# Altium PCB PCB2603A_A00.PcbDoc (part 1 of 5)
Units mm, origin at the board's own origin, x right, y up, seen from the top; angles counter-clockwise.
Board outline 35.56 x 55.88 mm, 8 copper layers (Top Layer, Signal Layer 1, Signal Layer 2, Signal Layer 3, Signal Layer 4, Signal Layer 5, Signal Layer 6, Bottom Layer), stack 1.497 mm thick; 167 components, 113 nets, 4957 pads, 645 vias.
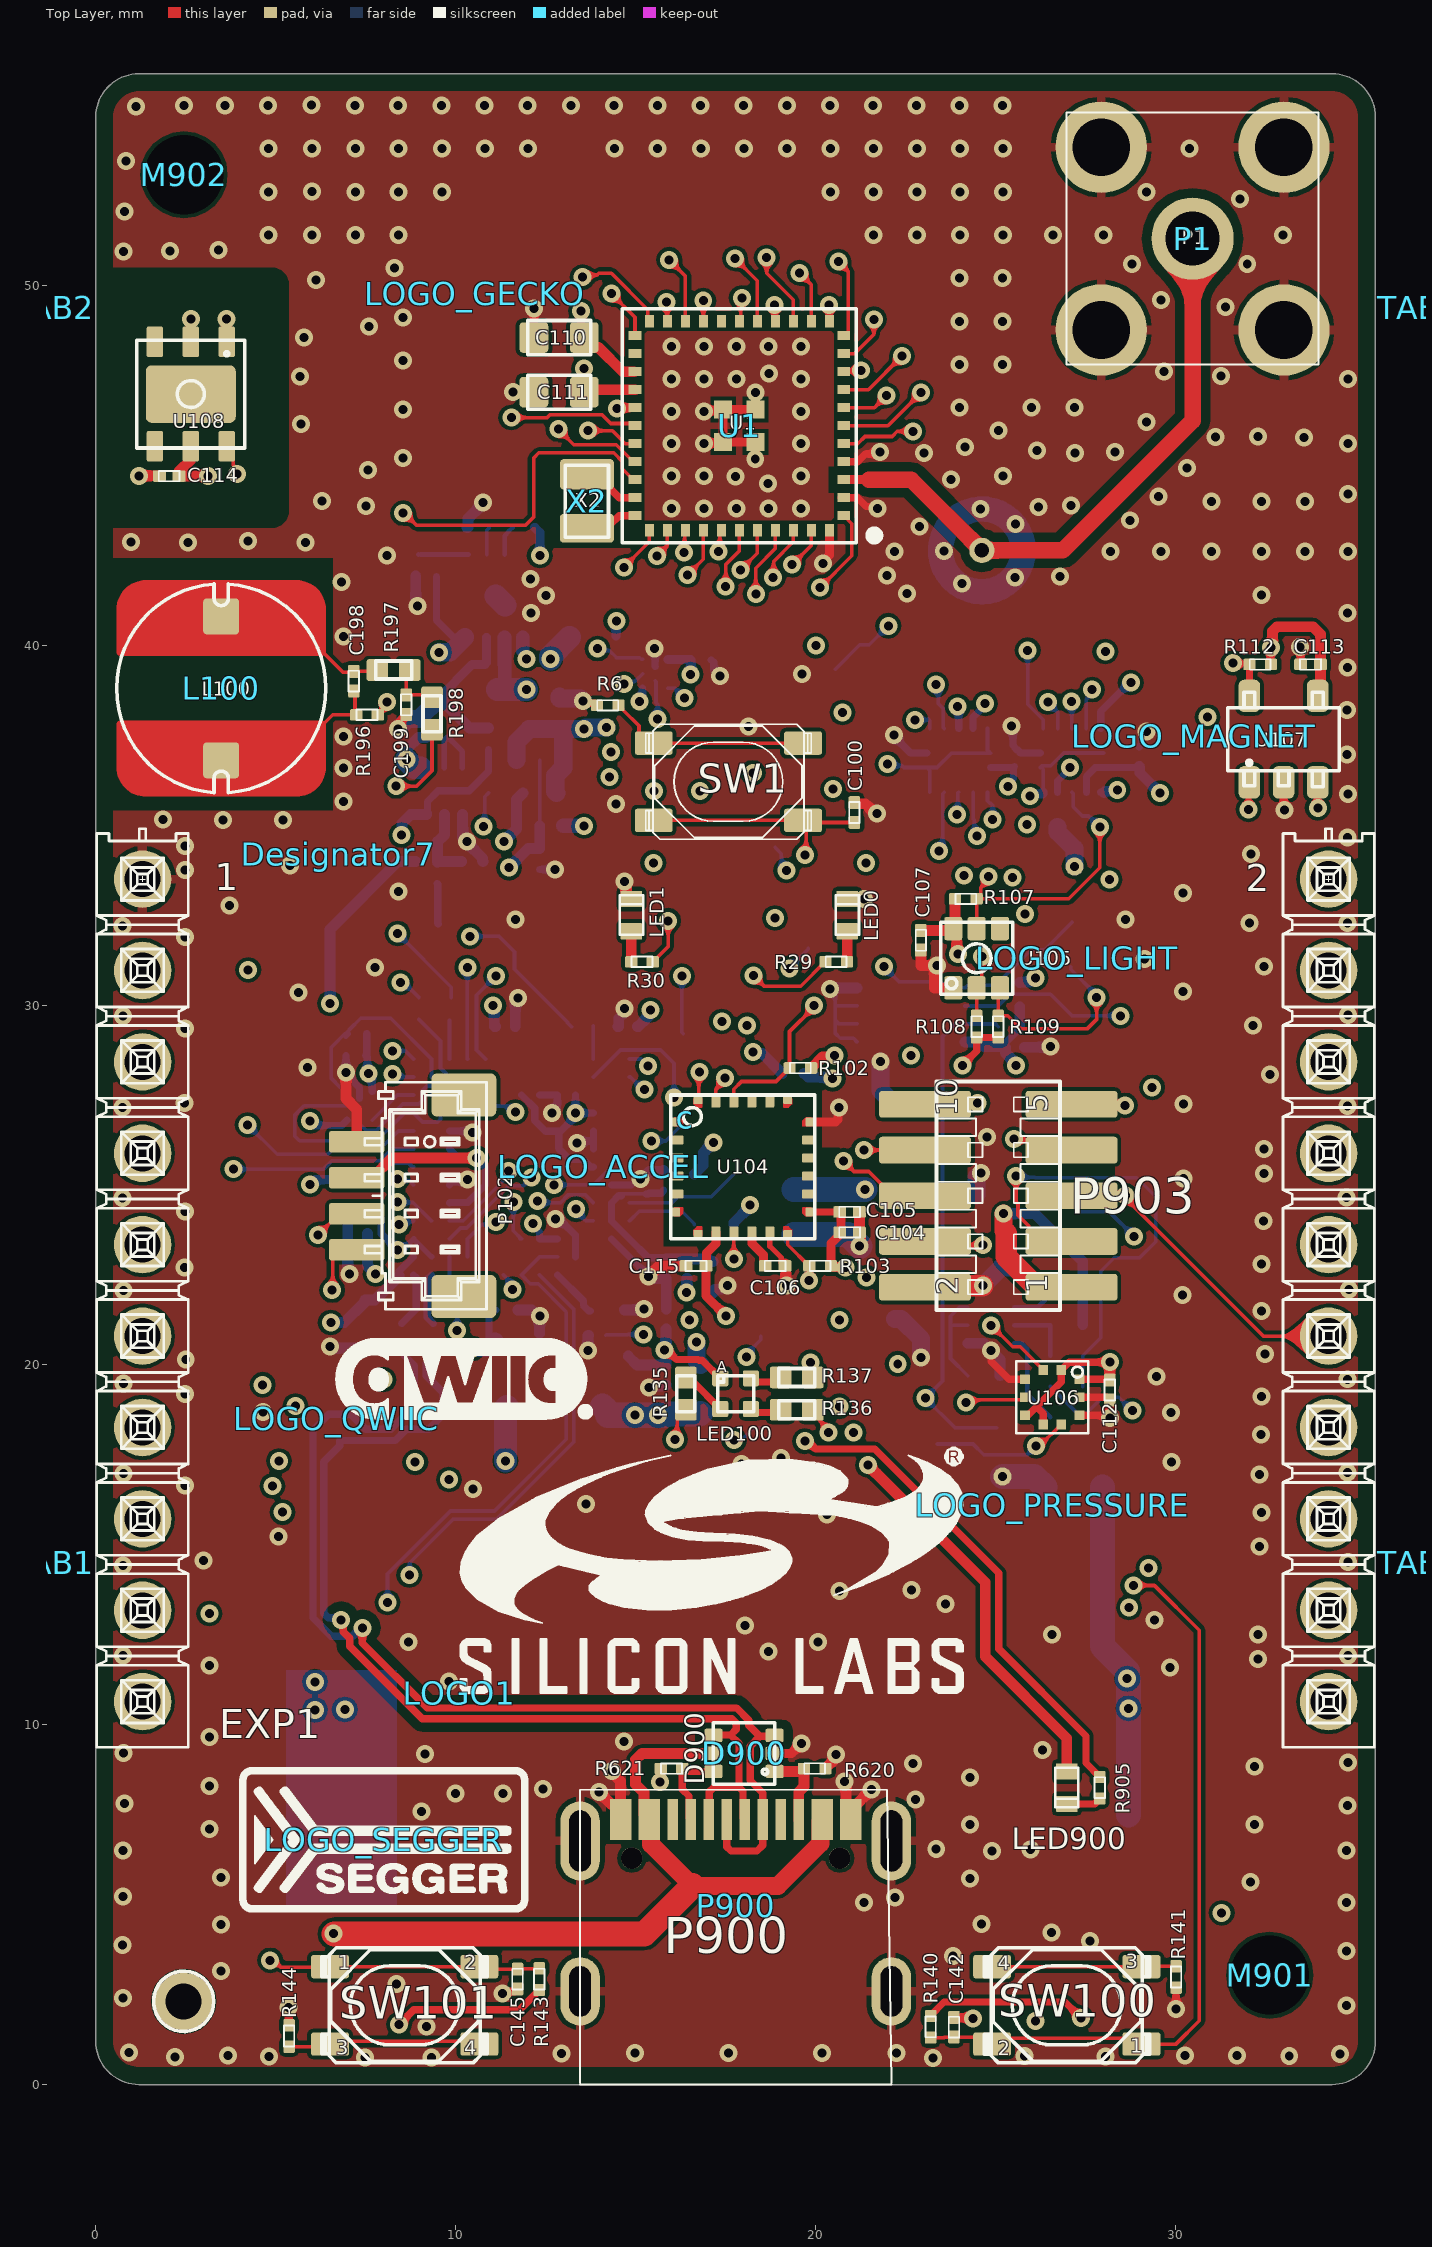
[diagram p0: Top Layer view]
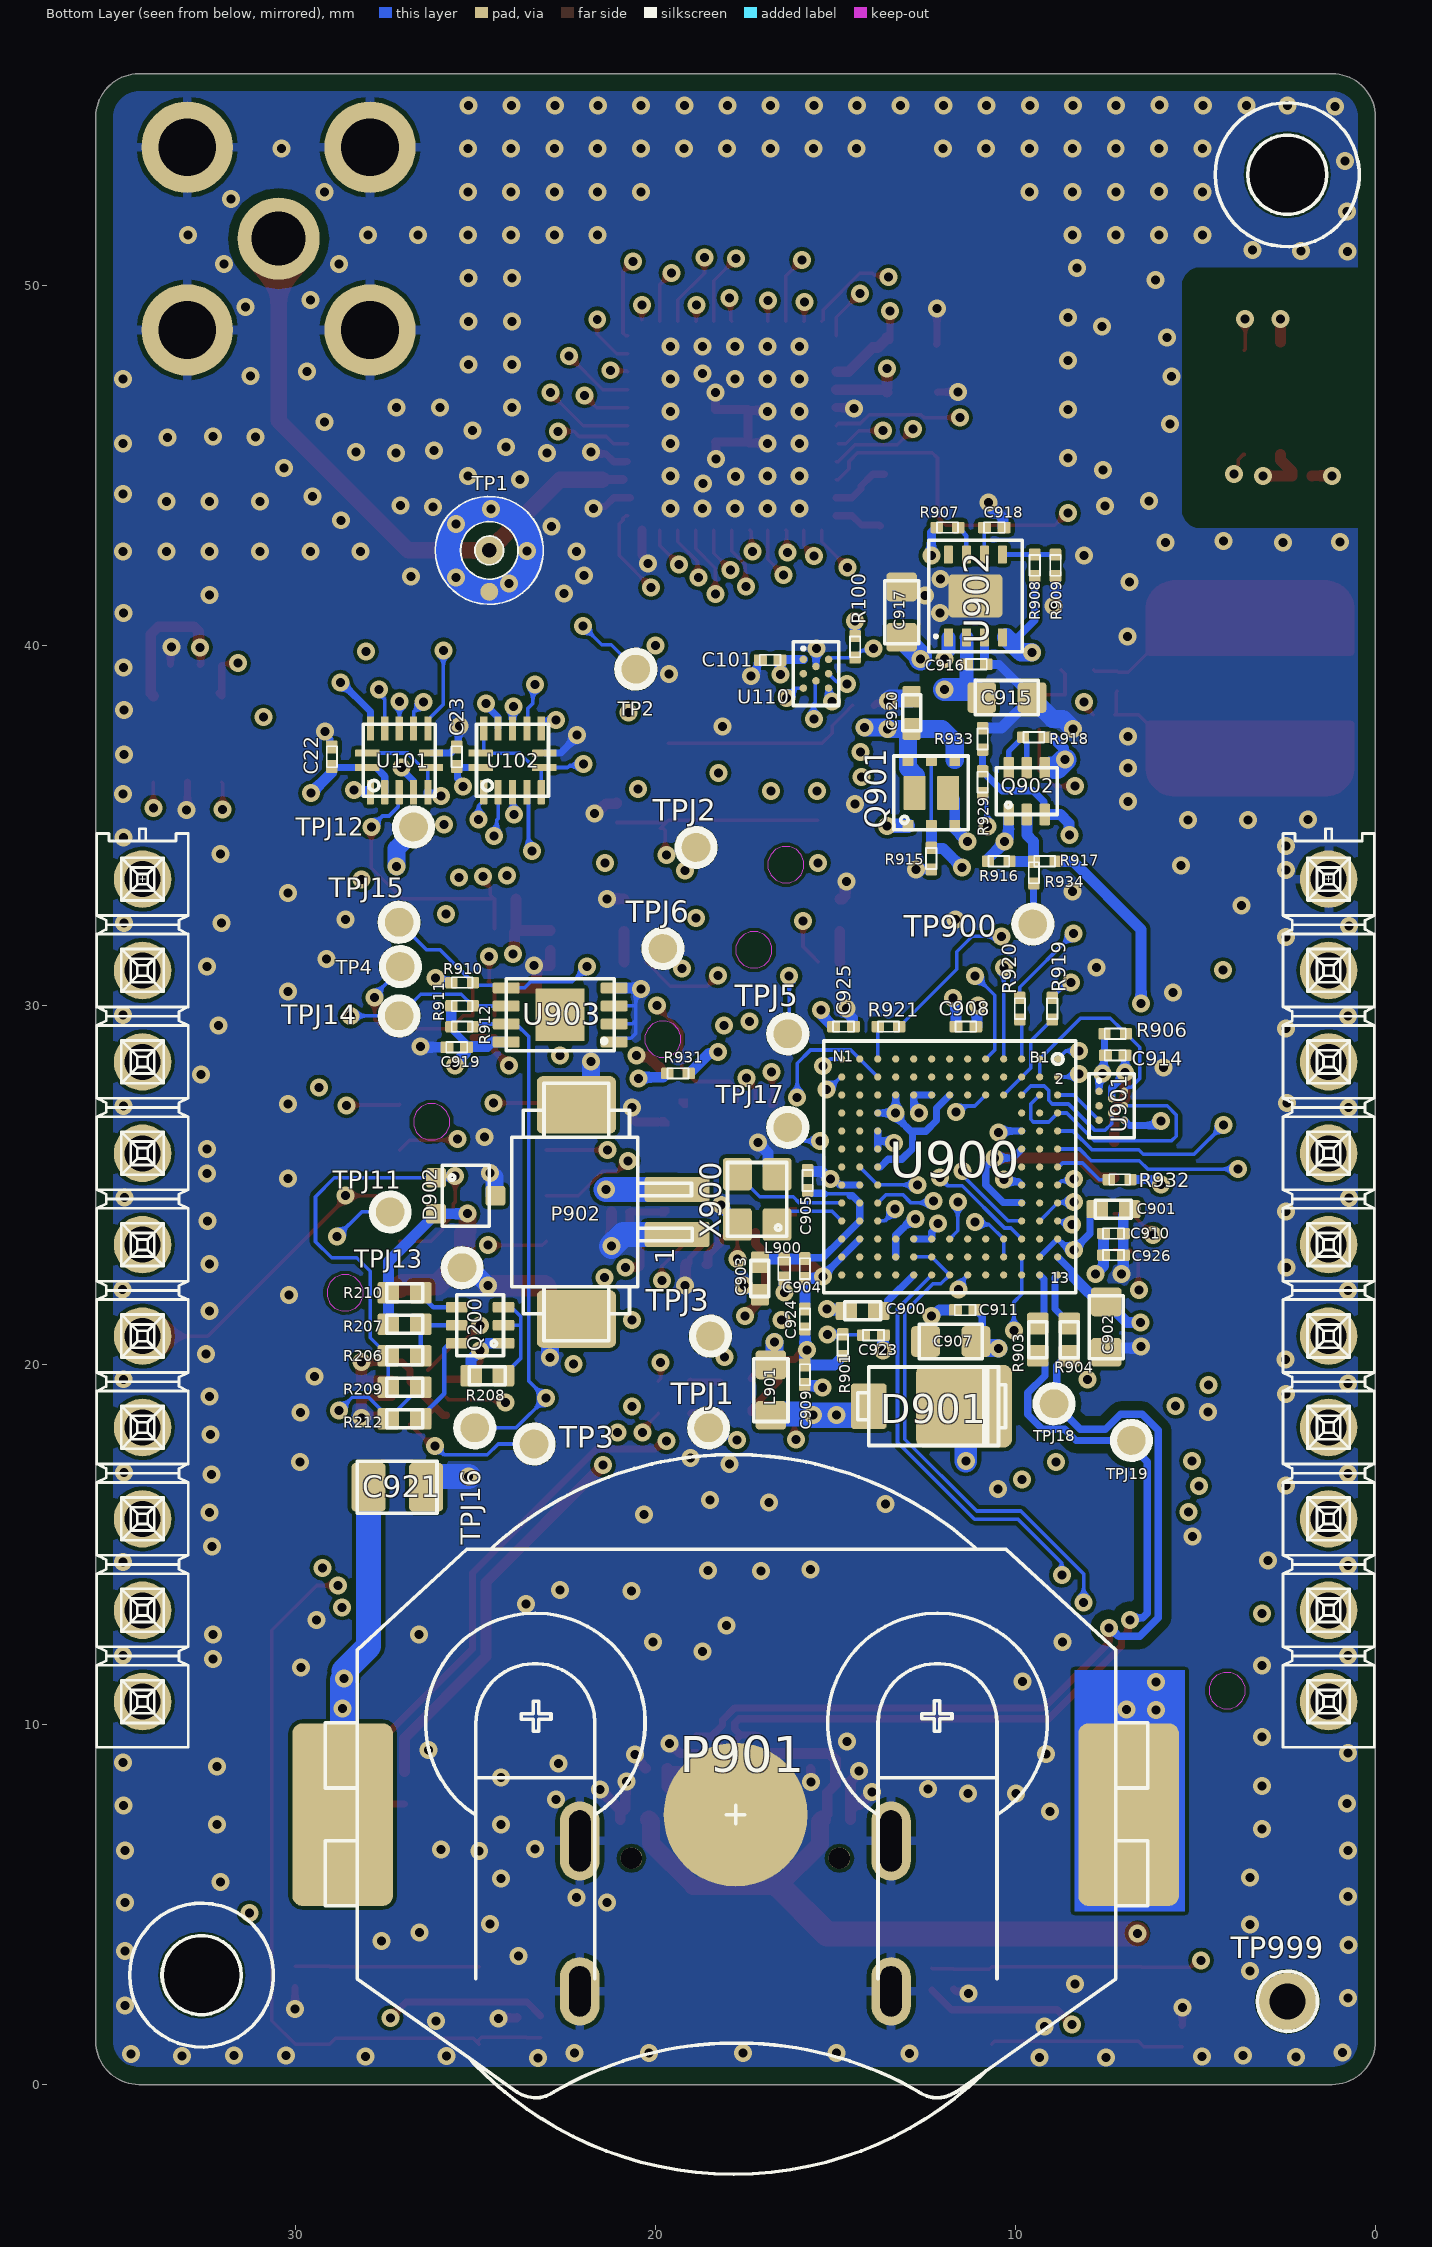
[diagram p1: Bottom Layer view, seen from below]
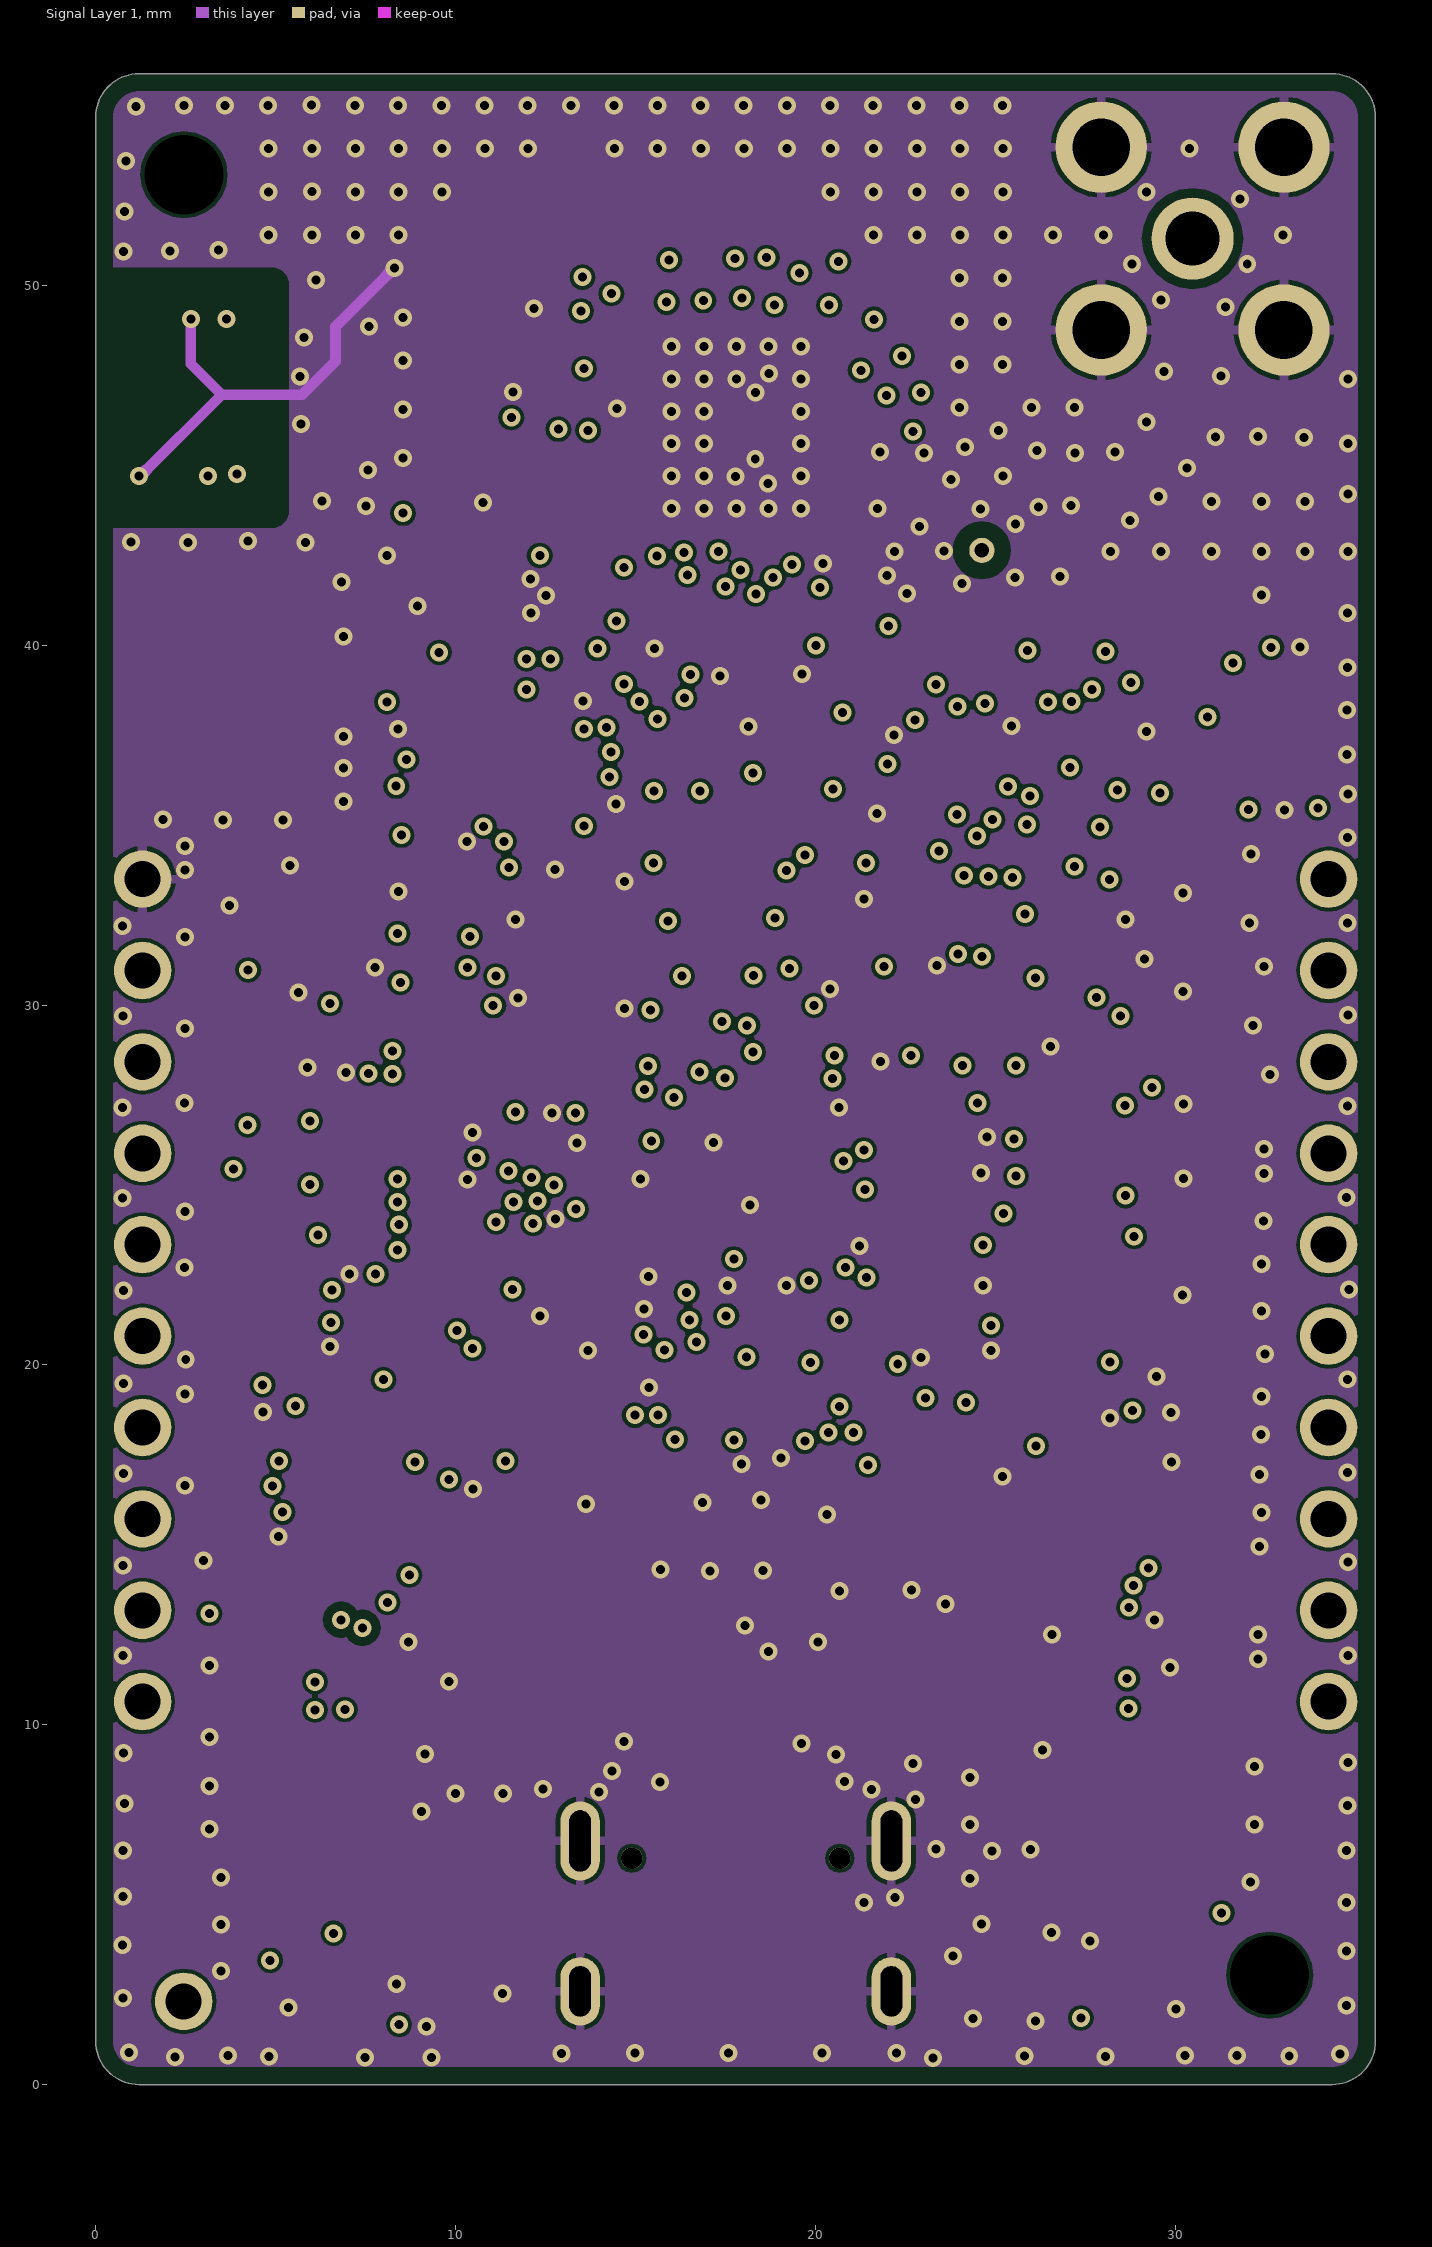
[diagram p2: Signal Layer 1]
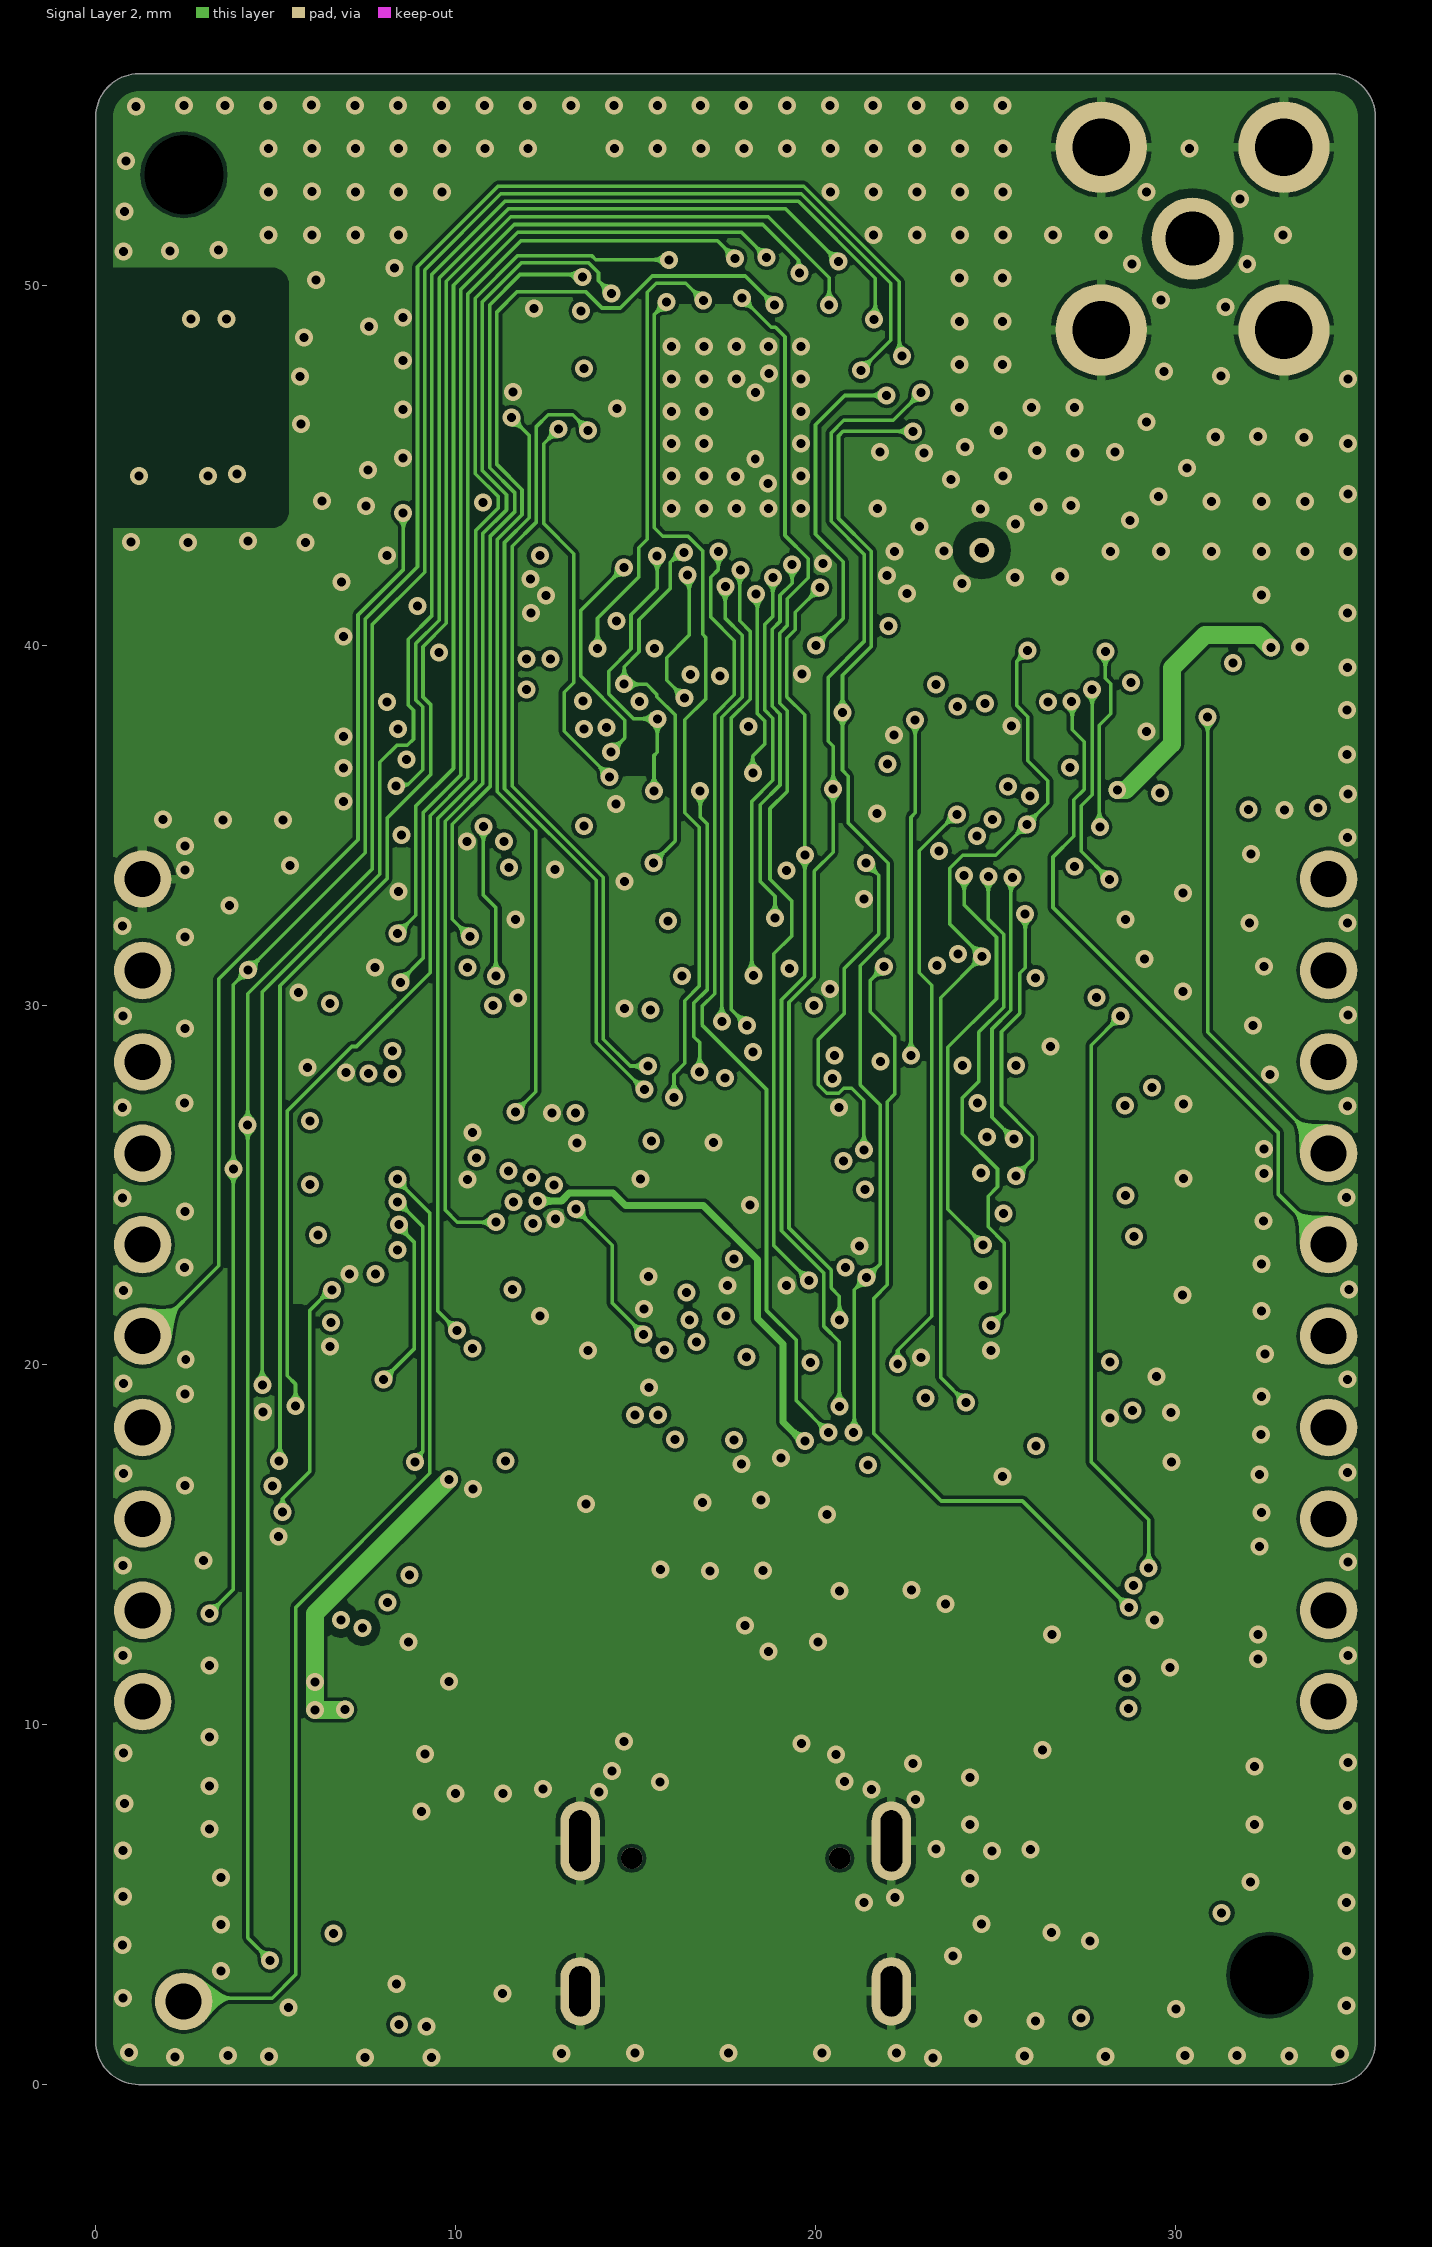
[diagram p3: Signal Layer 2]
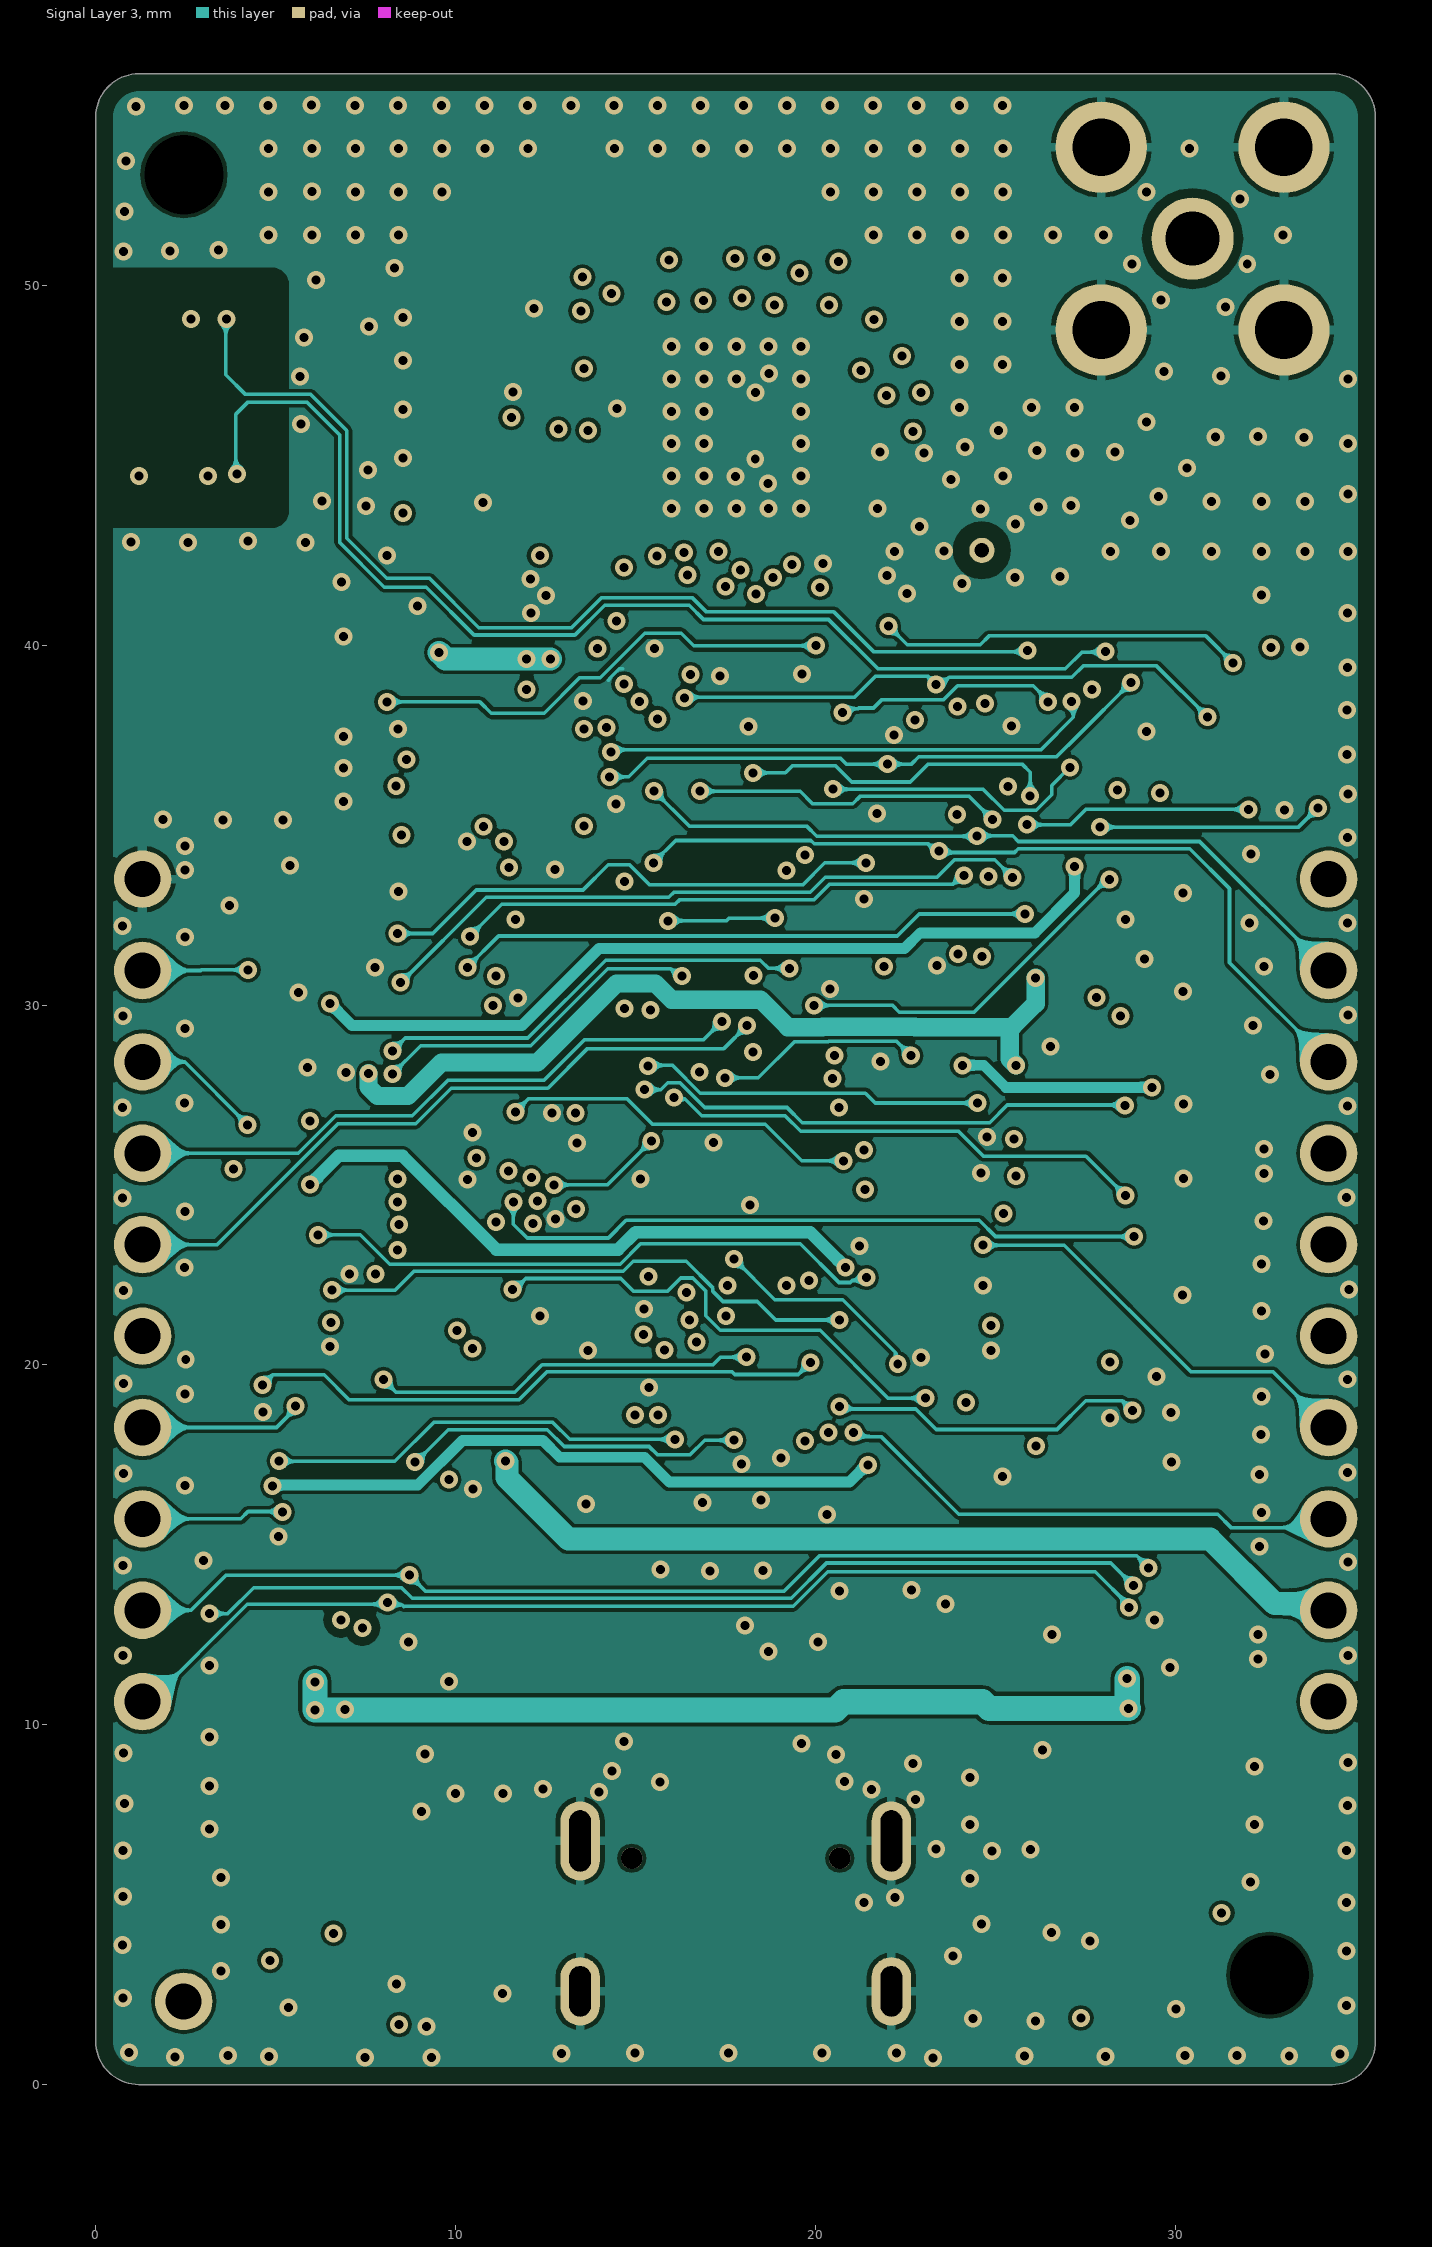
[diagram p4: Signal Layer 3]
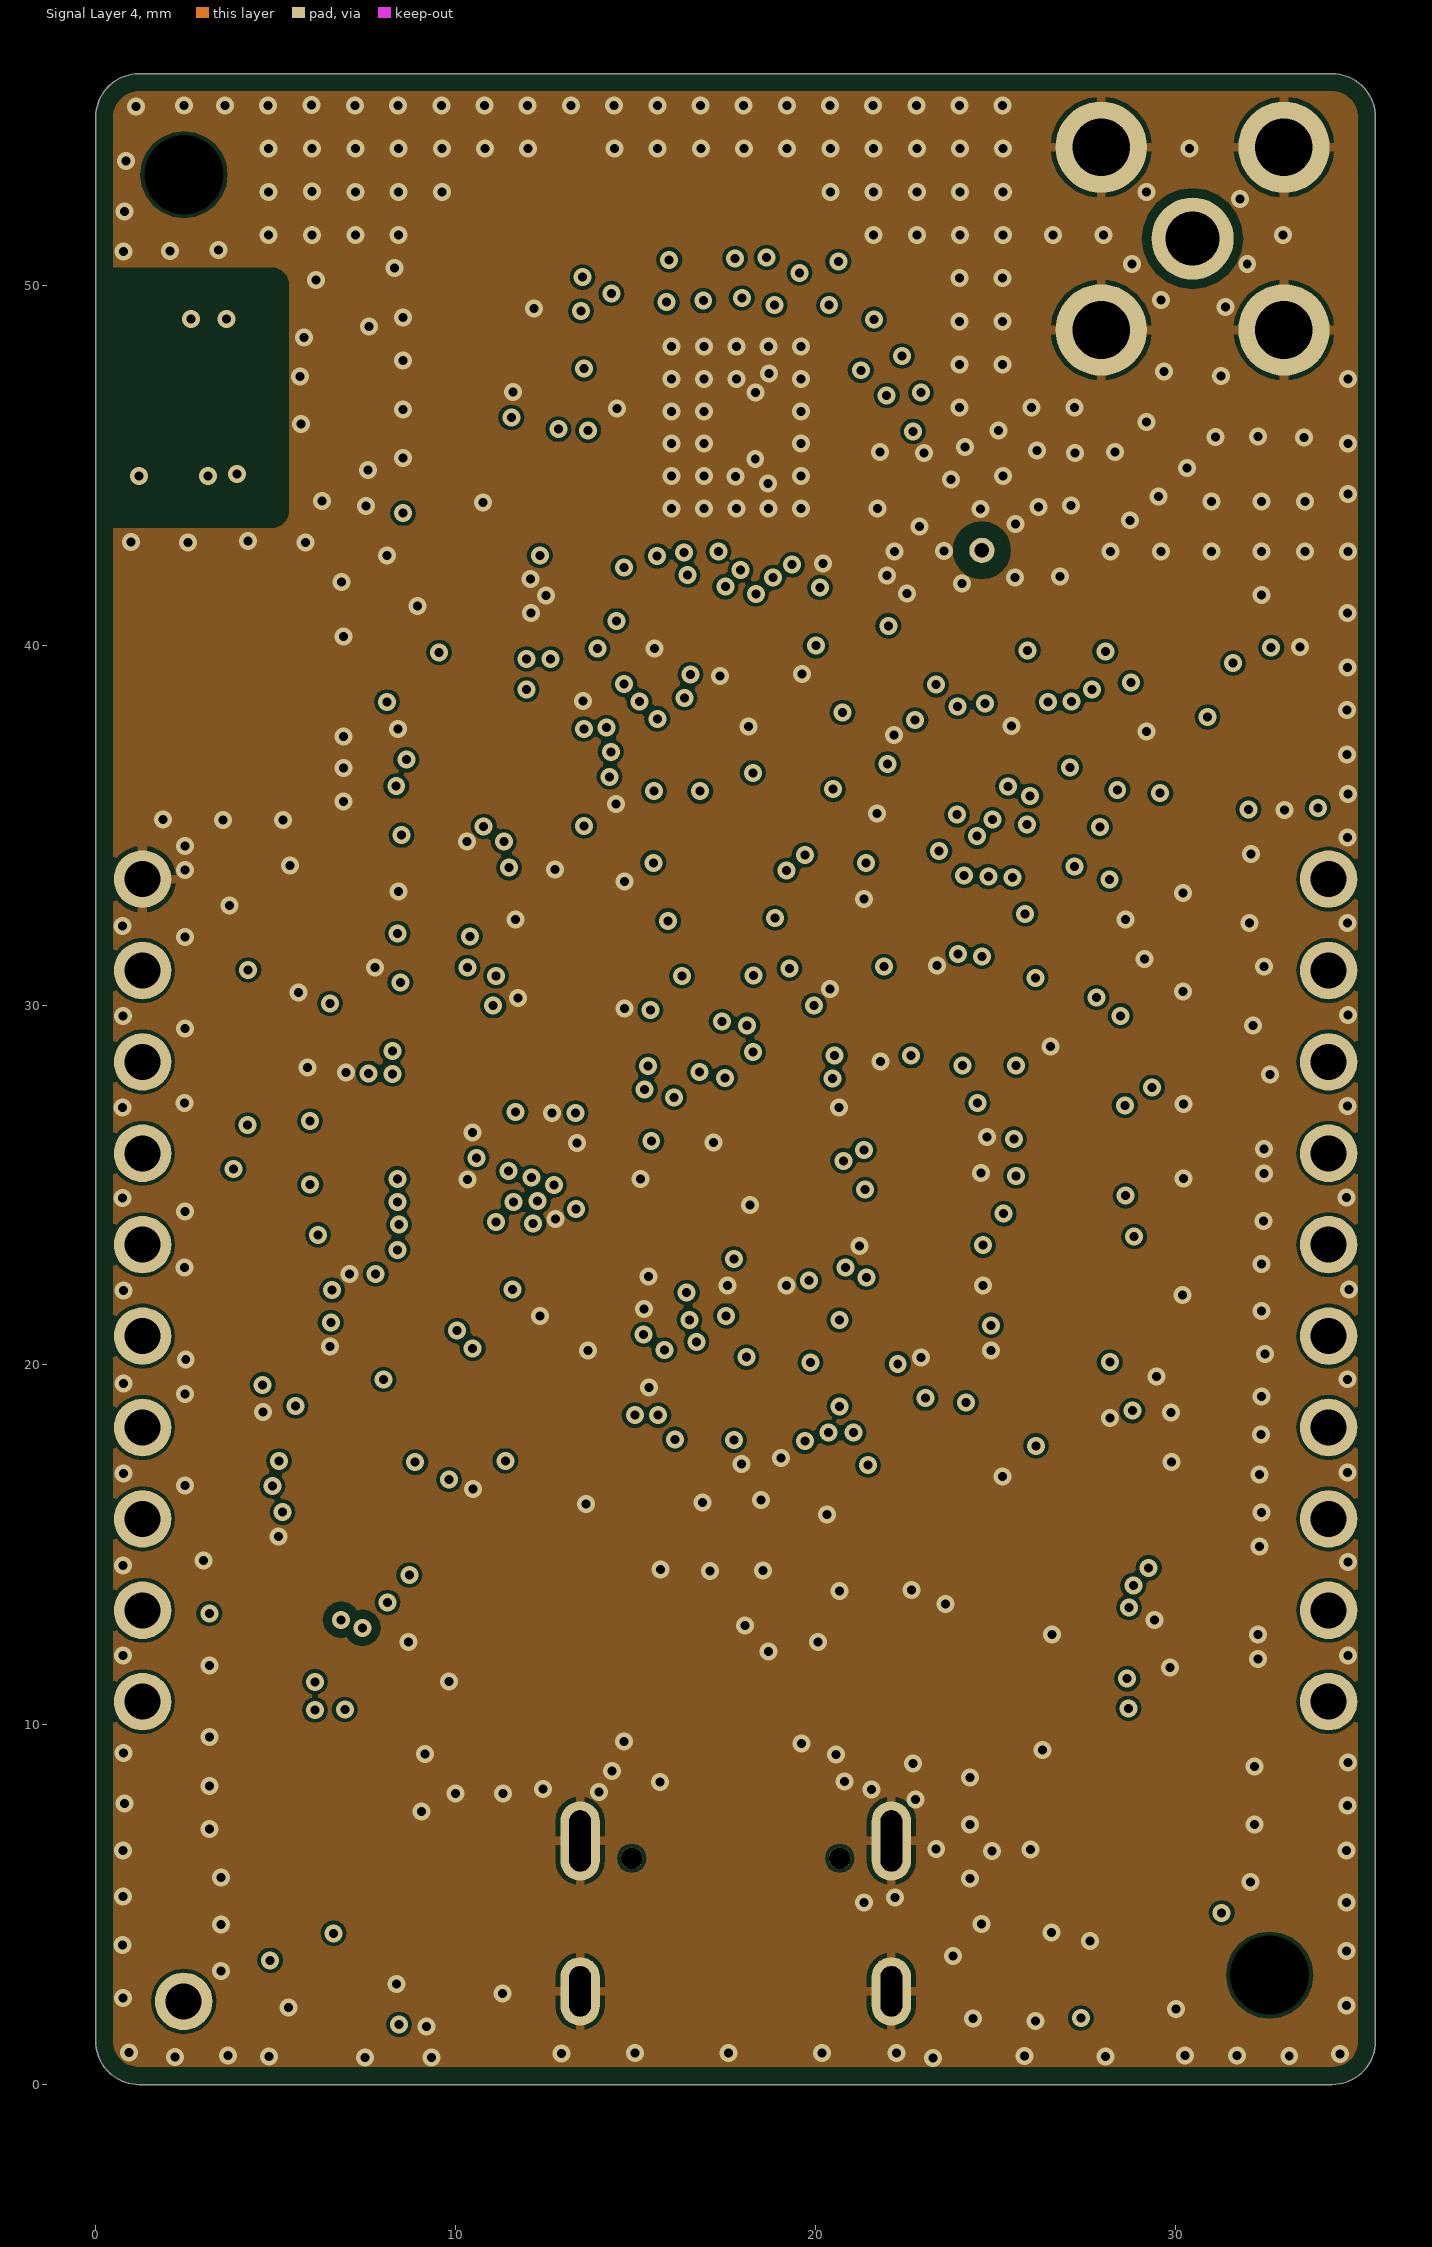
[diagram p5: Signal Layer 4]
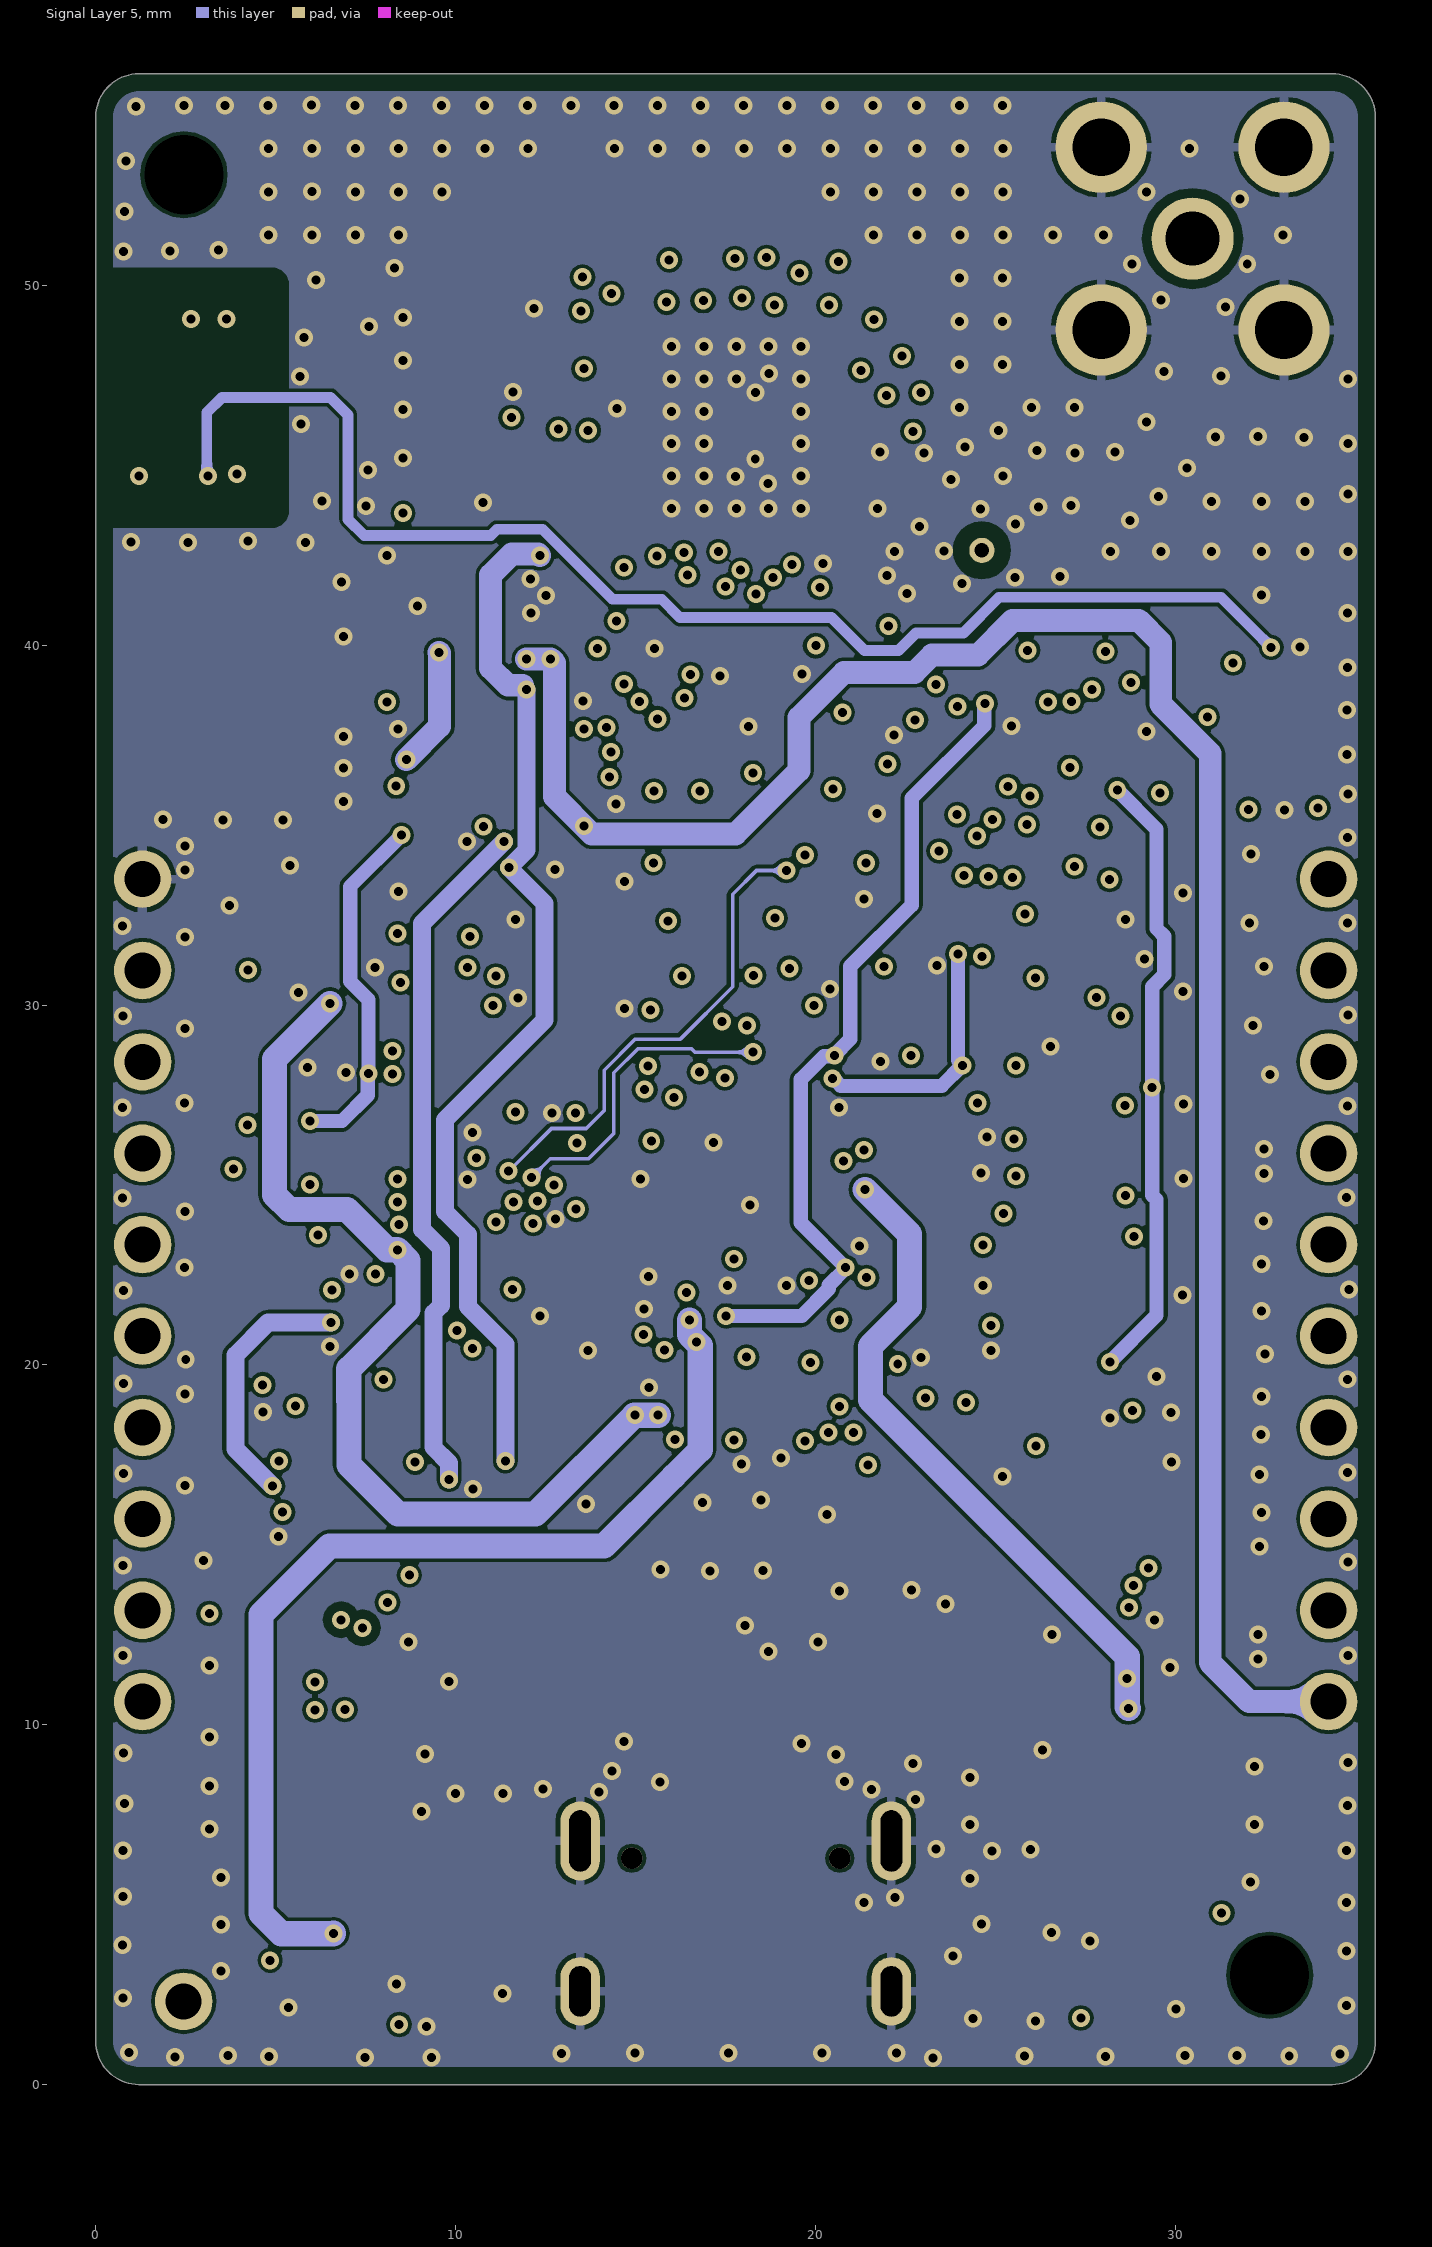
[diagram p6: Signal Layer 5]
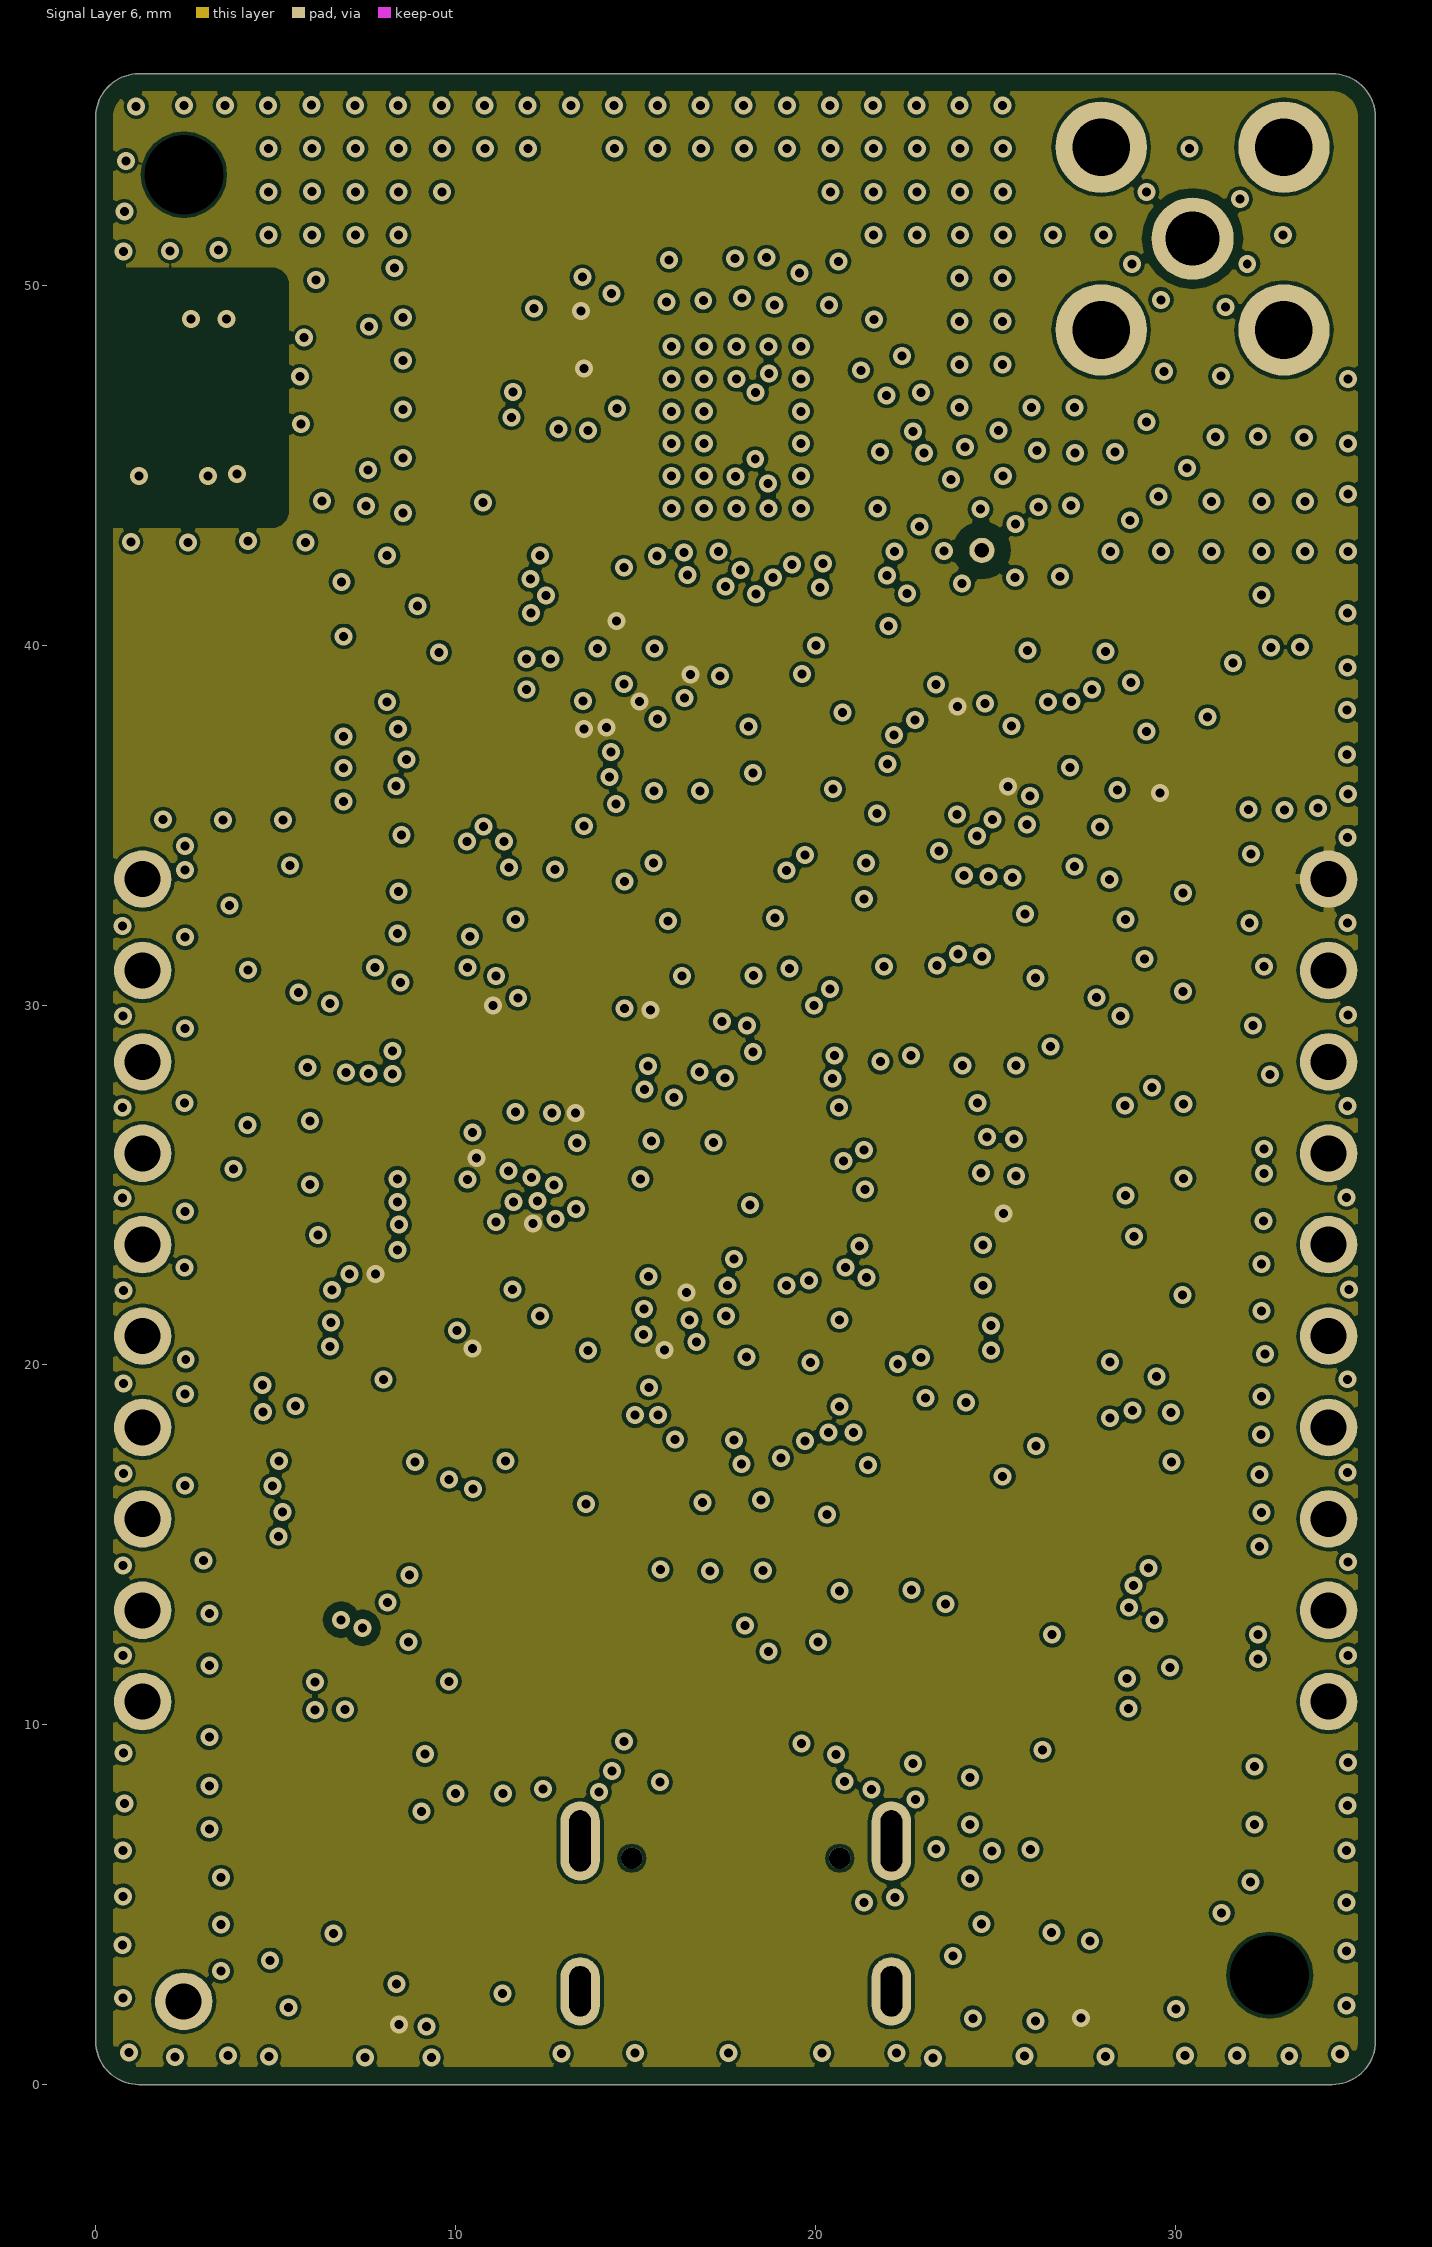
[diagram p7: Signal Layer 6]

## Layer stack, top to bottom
Top Solder: solder mask 0.05, Solder Resist, Dk 3.5
Top Layer: signal copper 0.038
Dielectric 1: core 0.304, FR-4, Dk 4.2
Signal Layer 1: signal copper 0.018
Dielectric 3: prepreg 0.1, PP-006, Dk 4.1
Signal Layer 2: signal copper 0.018
Dielectric 2: prepreg 0.1, FR-4, Dk 4.2
Signal Layer 3: signal copper 0.018
Dielectric 4: prepreg 0.3, FR-4, Dk 4.2
Signal Layer 4: signal copper 0.035
Dielectric 6: prepreg 0.1, FR-4, Dk 4.2
Signal Layer 5: signal copper 0.018
Dielectric 5: prepreg 0.0711, PP-006, Dk 4.1
Signal Layer 6: signal copper 0.035
Dielectric  7: core 0.304, FR-4, Dk 4.2
Bottom Layer: signal copper 0.038
Bottom Solder: solder mask 0.05, Solder Resist, Dk 3.5

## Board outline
0,1.2 0,54.68 cw(c1.2,54.68) 1.2,55.88 34.36,55.88 cw(c34.36,54.68) 35.56,54.68 35.561,54.68 35.561,1.2 35.56,1.2 cw(c34.36,1.2) 34.36,0 1.2,0 cw(c1.2,1.2)

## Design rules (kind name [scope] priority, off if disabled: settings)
AcuteAngle [All] p1: minimum=4.00000000000000E+0001 checktracksonly=FALSE
BoardOutlineClearance BoardOutlineClearance_IGNORE_Silk [OnSilkscreen] p1: gap=0 ignorepadtopadclearanceinfootprint=FALSE
BoardOutlineClearance [All] p2: gap=0.48 ignorepadtopadclearanceinfootprint=FALSE except(0.25: Arc-CutoutEdge Track-CutoutEdge SMDPad-CutoutEdge THPad-CutoutEdge Via-CutoutEdge Fill-CutoutEdge Poly-CutoutEdge Region-CutoutEdge Text-CutoutEdge)
Clearance USB [InNetClass('Differentialpair') vs InPolygon] p1: gap=0.25 ignorepadtopadclearanceinfootprint=FALSE
Clearance Clearance_1 [InComponent('TP1') vs (InLayerClass('50R_P1_INNER LAYERS'))] p2: gap=0.25 ignorepadtopadclearanceinfootprint=FALSE except(0: Arc-Hole Track-Hole SMDPad-Hole THPad-Hole Via-Hole Fill-Hole Poly-Hole Region-Hole Text-Hole; 0.45: THPad-Fill THPad-Poly THPad-Region; 0.6: Arc-Fill Arc-Poly Arc-Region Track-Fill Track-Poly Track-Region)
Clearance Clearance_50R_P1 [InNet('50R_P1')] p3: gap=0.25 ignorepadtopadclearanceinfootprint=FALSE except(0: Arc-Hole Track-Hole SMDPad-Hole THPad-Hole Via-Hole Fill-Hole Poly-Hole Region-Hole Text-Hole)
Clearance "Stitching No Net_1" [IsStitchingVia and InNet('No Net') vs (IsVia and (Not IsStitchingVia)) Or IsPad] p4: gap=0.127 ignorepadtopadclearanceinfootprint=FALSE
Clearance "Stitching No Net" [IsStitchingVia and InNet('No Net') vs (IsVia and (Not IsStitchingVia)) Or IsPad] p5: gap=0.127 ignorepadtopadclearanceinfootprint=FALSE
Clearance [All] p6: gap=0.1 ignorepadtopadclearanceinfootprint=FALSE except(0: Arc-Hole Track-Hole SMDPad-Hole THPad-Hole Via-Hole Fill-Hole Poly-Hole Region-Hole Text-Hole)
Clearance Clearance_RF [InNetClass('RF') vs InPolygon] p7: gap=0.25 ignorepadtopadclearanceinfootprint=FALSE except(0: Arc-Hole Track-Hole SMDPad-Hole THPad-Hole Via-Hole Fill-Hole Poly-Hole Region-Hole Text-Hole; 0.6: Arc-Fill Arc-Poly Arc-Region Track-Fill Track-Poly Track-Region SMDPad-Fill SMDPad-Poly SMDPad-Region THPad-Fill THPad-Poly THPad-Region Via-Fill Via-Poly Via-Region Fill-Fill Fill-Poly Fill-Region Poly-Poly Poly-Region Region-Region)
Clearance Clearance_NPL_Mic [((ObjectKind = 'Pad') And (Layer = 'MultiLayer') And (PadIsPlated = 'False')) and HasFootprint('MIC_INVENSENSE_ICS-43434') vs OnLayer('Bottom Layer')] p8: gap=0.2 ignorepadtopadclearanceinfootprint=FALSE except(0: Arc-Hole Track-Hole SMDPad-Hole THPad-Hole Via-Hole Fill-Hole Poly-Hole Region-Hole Text-Hole)
Clearance Clearance_NPL [(ObjectKind = 'Pad') And (Layer = 'MultiLayer') And (PadIsPlated = 'False')] p9: gap=0.25 ignorepadtopadclearanceinfootprint=FALSE except(0: Arc-Hole Track-Hole SMDPad-Hole THPad-Hole Via-Hole Fill-Hole Poly-Hole Region-Hole Text-Hole)
ComponentClearance [All] p1: gap=0 collisioncheckmode=3 verticalgap=0 showdistances=FALSE
HoleToHoleClearance HoleToHoleClearance_ANT1toPAD [Incomponent ('ANT1') vs ISpad] p1: gap=0 allowstackedmicrovias=TRUE
HoleToHoleClearance HoleToHoleClearance_P5toSW4 [Incomponent ('P5') vs Incomponent ('SW4')] p2: gap=0 allowstackedmicrovias=TRUE
HoleToHoleClearance HoleToHoleClearance_R1toR2 [Incomponent ('R1') vs Incomponent ('R2')] p3: gap=0 allowstackedmicrovias=TRUE
HoleToHoleClearance HoleToHoleClearance_general [All] p4: gap=0.375 allowstackedmicrovias=TRUE
MinimumSolderMaskSliver MinimumSolderMaskSliver_IGNORE_BGA8 [HasFootprint('BGA8_M040_1.24x1.75_WLCSP') vs HasFootprint('BGA8_M040_1.24x1.75_WLCSP')] p1: minsoldermaskwidth=0
MinimumSolderMaskSliver [not HasFootprint('LOGO*') vs not HasFootprint('LOGO*')] p2: minsoldermaskwidth=0.152
PolygonConnect [InPadClass('GND')] p1: connectstyle=Direct reliefconductorwidth=0.254 reliefentries=4 polygonreliefangle="90 Angle" airgapwidth=0.254
PolygonConnect PolygonConnect_Throughhole_GND [IsThruPin vs InNet('GND')] p2: connectstyle=Relief reliefconductorwidth=0.254 reliefentries=4 polygonreliefangle="90 Angle" airgapwidth=0.125
PolygonConnect PolygonConnect_general [All] p3: thpad.connectstyle=Relief thpad.reliefconductorwidth=0.3 thpad.reliefentries=4 thpad.polygonreliefangle="90 Angle" thpad.airgapwidth=0.125 smdpad.connectstyle=NoConnect smdpad.reliefconductorwidth=0.33 smdpad.reliefentries=4 smdpad.polygonreliefangle="90 Angle" smdpad.airgapwidth=0.102 via.connectstyle=Direct via.reliefconductorwidth=0.33 via.reliefentries=4 via.polygonreliefangle="90 Angle" via.airgapwidth=0.127
RoutingVias [All] p1: holewidth=0.25 width=0.508 viastyle="Through Hole" minholewidth=0.25 minwidth=0.508 maxholewidth=1 maxwidth=1.5 useviatemplates=TRUE viatemplateguid#1={3A37D5D4-6EF9-41F7-AE12-89C7EBFE3D30} viatemplatename#1=v50h25m0mx0
ShortCircuit ShortCircuit_ANTtoPAD [InNet('NetAT1_1') vs InNet('GND')] p1: allowed=TRUE
ShortCircuit ShortCircuit_General [All] p2: allowed=FALSE
SilkToSilkClearance [All] p1: silktosilkclearance=0.102
SilkToSolderMaskClearance [IsPad] p1: minsilkscreentomaskgap=0.102 clearancetoexposedcopper=TRUE
SolderMaskExpansion [All] p1: expansion=0.05 istentingtop=FALSE
UnRoutedNet [All] p1: checkbadconnections=TRUE
Width [All] p1: maxlimit=5.08 minlimit=0.1 preferedwidth=0.1
23 further rules are at their usual default settings.

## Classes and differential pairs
net class 50R_P1: 50R_P1
pad class GND: C917-2 P901-2 U902-9
net class Differentialpair: DBG_USB_DM DBG_USB_DP

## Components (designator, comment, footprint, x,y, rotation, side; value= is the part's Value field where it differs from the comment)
c "Comment" TESTJIGG_PCB4166_MECH2_SL 18.53,18.25 r0 top locked
C22 "100N" C0201_L 29,36.9 r90 bottom
C23 "100N" C0201_L 25.53,36.9 r90 bottom
C100 "100N" C0201_L 21.083,35.348 r90 top
C101 "100N" C0201_L 16.819,39.588 r0 bottom
C104 "2U2" C0201_L 20.95,23.682 r0 top
C105 "100N" C0201_L 20.95,24.25 r0 top
C106 "470N" C0201_L 18.88,22.75 r0 top
C107 "100N" C0201_L 22.93,31.8 r270 top
C110 "10U" C0603_L 12.875,48.55 r180 top
C111 "10U" C0603_L 12.875,47.032 r180 top
C112 "100N" C0201_L 28.18,19.3 r270 top
C113 "100N" C0201_L 33.76,39.465 r180 top
C114 "100N" C0201_L 2.04,44.7 r180 top
C115 "10N" C0201_L 16.68,22.75 r180 top
C142 "1N" C0201_L 23.85,1.594 r90 top
C145 "1N" C0201_L 11.72,2.93 r270 top
C198 "330P" C0201_L 7.171,39 r270 top
C199 "100N" C0201_L 8.625,38.345 r270 top
C900 "1U" C0402_L 14.25,21.5 r0 bottom
C901 "1U" C0402_L 7.28,24.325 r180 bottom
C902 "4U7" C0603_L 7.48,21.05 r270 bottom
C903 "1U" C0402_L 17.105,22.4 r270 bottom
C904 "10N" C0201_L 15.855,22.675 r270 bottom
C905 "10N" C0201_L 15.78,25.125 r90 bottom
C907 "4U7" C0603_L 11.8,20.65 r0 bottom
C908 "100N" C0201_L 11.38,29.4 r0 bottom
C909 "100N" C0201_L 15.855,19.725 r270 bottom
C910 "100N" C0201_L 7.28,23.65 r180 bottom
C911 "100N" C0201_L 11.4,21.525 r0 bottom
C914 "100N" C0201_L 7.23,28.6 r180 bottom
C915 "4U7" C0603_L 10.24,38.545 r180 bottom
C916 "100N" C0201_L 11.09,39.47 r180 bottom
C917 "10U" C0603_L 13.165,40.92 r90 bottom
C918 "33N" C0201_L 10.59,43.27 r180 bottom
C919 "100N" C0201_L 25.53,28.825 r0 bottom
C920 "1U" C0402_L 12.89,38.12 r90 bottom
C921 "47U" C0805_L 27.18,16.6 r180 bottom
C923 "100N" C0201_L 13.95,20.825 r180 bottom
C924 "100N" C0201_L 15.855,21.275 r90 bottom
C925 "100N" C0201_L 14.78,29.4 r180 bottom
C926 "100N" C0201_L 7.28,23.05 r180 bottom
D900 "DT1446-04" SOT563_DIODES 18.015,9.2 r180 top
D901 "SS3P3" DO220AA 12.28,18.85 r0 bottom
D902 "ESD" SOT663_NXP 25.28,24.7 r180 bottom
Designator7 "Comment" LOGO_LC_SENSOR_SYMBOL 6.735,34.2 r0 top
EXP1 "HEADER_2X10_2.54MM_TH_SPLIT" HDR_M254-1X10_PLUS_1X10_NO_3D 34.261,33.5 r270 top locked
L100 "470uH" COIL_BOURNS_SDR0604 3.485,38.8 r270 top
L900 "742692004" COIL_0201_L 16.43,22.675 r90 bottom
L901 "742792662" WURTH_CBF_0603 16.8,19.3 r270 bottom
LED0 "YELLOW" LED_0402_CAT2 20.885,32.5 r90 top
LED1 "YELLOW" LED_0402_CAT2 14.885,32.5 r90 top
LED100 "RGB" LED_LUMEX_SML-LX0404-4 17.78,19.2 r270 top
LED900 "BLUE" LED_0402_CAT2 26.985,8.25 r270 top
LOGO1 "Comment" LOGO_SILABS_W14.0 10.105,10.87 r0 top
LOGO_ACCEL "Comment" LOGO_ACCEL_SM 14.1,25.5 r0 top
LOGO_GECKO "Comment" LOGO_GECKO_H4.0_SM 10.53,49.773 r0 top locked
LOGO_LIGHT "Comment" LOGO_LIGHT_SM 27.28,31.3 r0 top
LOGO_MAGNET "Comment" LOGO_MAGNET_SM 30.509,37.471 r90 top
LOGO_PRESSURE "Comment" LOGO_PRESSURE 26.58,16.1 r0 top locked
LOGO_QWIIC "Comment" LOGO_QWIIC_GM21_W7.0 6.68,18.5 r0 top locked
LOGO_SEGGER "LOGO_SEGGER_10.0X5.0_SM" LOGO_SEGGER_8.0X4.0_SM 8,6.8 r0 top
M901 "2.2 MM" HOLE_2.2_NPL 32.621,3.04 r0 top locked
M902 "2.2 MM" HOLE_2.2_NPL 2.45,53.075 r0 top locked
P1 "SMA" TE_SMA_1814832_TH_VER 30.48,51.3 r90 top
P102 "QWIIC 4P" WCON_WF1001A-WM04E-4 10.23,24.7 r270 top locked
P900 "BEC_80259-1021" BEC_80259-1021 17.785,0.5 r0 top
P901 "CR2032" BAT_HOLD_MPD_BK-912_CR2032_4166-1-2 17.78,7.5 r180 bottom locked
P902 "DF13C-2P-1.25V" HRS_DF13C-2P-1.25V 20.805,24.25 r90 bottom locked
P903 "MINI-SIMPLICITY" FTSH_105_01_L_DV_K 25.08,24.7 r90 top locked
Q200 "DMC2400UV" SOT563_L 24.88,21.1 r0 bottom
Q901 "SiA527DJ" POWERPAK_SC70-6_L 12.34,35.895 r90 bottom
Q902 "DMC2400UV" SOT563_L 9.69,35.945 r90 bottom
R6 "100R" R0201_L 14.227,38.328 r0 top
R29 "2K7" R0201_L 20.577,31.2 r180 top
R30 "2K7" R0201_L 15.181,31.2 r0 top
R100 "330K" R0201_L 14.46,39.955 r90 bottom
R102 "100K" R0201_L 19.58,28.25 r180 top
R103 "100K" R0201_L 20.13,22.75 r180 top
R107 "2K8" R0201_L 24.18,32.95 r0 top
R108 "2K8" R0201_L 24.48,29.4 r90 top
R109 "100K" R0201_L 25.08,29.4 r90 top
R112 "100K" R0201_L 32.36,39.465 r180 top
R135 "698R" R0402_L 16.4,19.2 r270 top
R136 "910R" R0402_L 19.48,18.75 r0 top
R137 "2K32" R0402_L 19.48,19.65 r0 top
R140 "1M" R0201_L 23.2,1.604 r270 top
R141 "100R" R0201_L 30.022,2.99 r270 top
R143 "1M" R0201_L 12.325,2.93 r90 top
R144 "100R" R0201_L 5.372,1.348 r90 top
R196 "1K5" R0201_L 7.536,38.064 r180 top
R197 "0R" R0402_L 8.276,39.31 r0 top
R198 "100R" R0402_L 9.344,38.1 r90 top
R206 "100R" R0402_L 26.98,20.25 r180 bottom
R207 "10K" R0402_L 26.98,21.125 r0 bottom
R208 "10K" R0402_L 24.68,19.7 r180 bottom
R209 "0R" R0402_L 26.98,19.375 r180 bottom
R210 "0R" R0402_L 26.98,22 r0 bottom
R212 "100R" R0402_L 26.98,18.5 r0 bottom
R620 "5K1" R0201_L 19.979,8.781 r180 top
R621 "5K1" R0201_L 16,8.781 r0 top
R901 "1K" R0201_L 14.8,20.55 r270 bottom
R903 "33R" R0402_L 9.38,20.7 r90 bottom
R904 "33R" R0402_L 8.505,20.7 r90 bottom
R905 "5K76" R0201_L 27.9,8.25 r270 top
R906 "330K" R0201_L 7.23,29.2 r0 bottom
R907 "10K" R0201_L 11.89,43.27 r0 bottom
R908 "180K" R0201_L 9.465,42.22 r270 bottom
R909 "110K" R0201_L 8.89,42.22 r90 bottom
R910 "4K7" R0201_L 25.38,30.625 r0 bottom
R911 "4K7" R0201_L 25.38,29.975 r0 bottom
R912 "10K" R0201_L 25.38,29.4 r0 bottom
R915 "470K" R0201_L 12.34,34.07 r90 bottom
R916 "10K" R0201_L 10.465,33.995 r180 bottom
R917 "1K" R0201_L 9.19,33.995 r180 bottom
R918 "330K" R0201_L 9.49,37.445 r180 bottom
R919 "470R" R0201_L 8.98,29.9 r90 bottom
R920 "470R" R0201_L 9.88,29.9 r90 bottom
R921 "470R" R0201_L 13.53,29.4 r180 bottom
R929 "1K" R0201_L 10.915,36.195 r90 bottom
R931 "1K" R0201_L 19.38,28.1 r0 bottom
R932 "1K" R0201_L 7.108,25.15 r180 bottom
R933 "4K7" R0201_L 10.915,37.395 r90 bottom
R934 "0R" R0201_L 9.489,33.677 r90 bottom
SW1 "PTS810" SW_CK_PTS810 17.58,36.205 r180 top
SW100 "PTS810" SW_CK_PTS810 26.985,2.2 r180 top
SW101 "PTS810" SW_CK_PTS810 8.585,2.2 r0 top
TAB1 "Comment" TAB50.5_T1.6_W2.4_SLIM__NOHOLES_SL -1.198,14.5 r90 top
TAB2 "Comment" TAB50.5_T1.6_W2.4_SLIM__NOHOLES_SL -1.198,49.38 r90 top
TAB3 "Comment" TAB50.5_T1.6_W2.4_SLIM__NOHOLES_SL 36.76,49.38 r90 top
TAB4 "Comment" TAB50.5_T1.6_W2.4_SLIM__NOHOLES_SL 36.76,14.5 r90 top
TP1 "TP_RF" "TP_INGUN_50_OHM_CLOSED OPENVIA" 24.625,42.635 r180 bottom
TP2 "TPJ_SMD" TP_1.0_SMD 20.555,39.334 r180 bottom
TP3 "TPJ_SMD" TP_1.0_SMD 23.38,17.8 r180 bottom
TP4 "TPJ_SMD" TP_1.0_SMD 27.097,31.068 r180 bottom
TP900 "TPJ_SMD" TP_1.0_SMD 9.52,32.25 r90 bottom
TP999 "PROTO_TH" PROTO_TH 2.443,2.312 r180 bottom
TPJ1 "TPJ_SMD" TP_1.0_SMD 18.53,18.25 r90 bottom locked
TPJ2 "TPJ_SMD" TP_1.0_SMD 18.88,34.38 r90 bottom locked
TPJ3 "TPJ_SMD" TP_1.0_SMD 18.48,20.8 r90 bottom locked
TPJ5 "TPJ_SMD" TP_1.0_SMD 16.33,29.2 r90 bottom locked
TPJ6 "TPJ_SMD" TP_1.0_SMD 19.8,31.57 r90 bottom locked
TPJ11 "TPJ_SMD" TP_1.0_SMD 27.38,24.25 r90 bottom locked
TPJ12 "TPJ_SMD" TP_1.0_SMD 26.73,34.95 r90 bottom
TPJ13 "TP_SMD" TP_1.0_SMD 25.38,22.7 r90 bottom locked
TPJ14 "TPJ_SMD" TP_1.0_SMD 27.13,29.7 r90 bottom locked
TPJ15 "TPJ_SMD" TP_1.0_SMD 27.13,32.3 r90 bottom locked
TPJ16 "TPJ_SMD" TP_1.0_SMD 25.03,18.25 r90 bottom locked
TPJ17 "TPJ_SMD" TP_1.0_SMD 16.33,26.6 r90 bottom locked
TPJ18 "TPJ_SMD" TP_1.0_SMD 8.93,18.92 r90 bottom
TPJ19 "TPJ_SMD" TP_1.0_SMD 6.78,17.9 r90 bottom locked
U1 "ZGM230S" ZGM230S 17.885,46.1 r180 top
U101 "TS3A4751" QFN14_M040_2.0X2.0_TI_RUC 27.13,36.8 r90 bottom
U102 "TS3A4751" QFN14_M040_2.0X2.0_TI_RUC 23.98,36.8 r90 bottom
U104 "ICM-20689" QFN24_M050_4.0X4.0_NO_EP_ICM-20689 17.98,25.5 r0 top locked
U105 "VEML6035" SENS_VISH_VEML6035 24.48,31.3 r90 top locked
U106 "BMP384" BOSCH_BMP384_LGA10_M050_2.0X2.0 26.58,19.1 r0 top
U107 "Si7210" SOT23-5_L 33.01,37.39 r90 top locked
U108 "Si7021" DFN6_3X3MM_SI7021 2.64,46.98 r270 top
U110 "MX25R8035F" BGA8_3-2-3_M040_1.24x1.75_WLCSP 15.547,39.208 r180 bottom
U900 "EFM32GG12B410F1024GL120-A" BGA120_M050_7.0X7.0_SL_EFM32GG12 11.83,25.5 r270 bottom locked
U901 "MX25R8035F" BGA8_3-2-3_M040_1.24x1.75_WLCSP 7.33,27.2 r180 bottom locked
U902 "LP3982ILD-ADJ" LLP8_MA65_W3.0 11.115,41.37 r90 bottom
U903 "24AA024" TDFN8_M050_2.0X3.0_EP 22.655,29.725 r0 bottom locked
X2 "32.768kHz" X_MCS_CM8V-T1A 13.65,44 r90 top
X900 "48 MHz" X_SSS_DSX211SH_2.05X1.65-4 17.18,24.6 r90 bottom
? "Comment" LOGO_HUMID_3.2X3.2_SM 7,46.75 r0 top

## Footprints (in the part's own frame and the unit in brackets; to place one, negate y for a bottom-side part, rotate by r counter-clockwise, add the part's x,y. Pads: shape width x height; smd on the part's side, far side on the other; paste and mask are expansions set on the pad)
BAT_HOLD_MPD_BK-912_CR2032_4166-1-2 [mil] "MPD Battery Holder BK-912 (for CR2032)"
  rrect20% 110x200 smd: 1(-430,0) 1(430,0)
  round 157.48 smd paste-295.67 mask-82.68: 2(0,0)
  silkscreen extent -449,-393 451,394, body extent -415,-311 417,291, height 175
BEC_80259-1021 [mm] "Amphenol FCI, 10118194-000XLF, Micro USB Type B"
  round 0.6 hole 0.6 unplated mask+0: 1(-2.89,5.79) 2(2.89,5.79)
  rect 0.6x1.14 smd mask+0.05: A1_B12(-3.2,6.86) A4_B9(-2.4,6.86) B1_A12(3.2,6.86) B4_A9(2.4,6.86)
  rect 0.3x1.14 smd mask+0.05: A5(-1.25,6.86) A6(-0.25,6.86) A7(0.25,6.86) A8(1.25,6.86) B5(1.75,6.86) B6(0.75,6.86) B7(-0.75,6.86) B8(-1.75,6.86)
  oval 1.1x2.2 hole 0.6 slot 1.7 at 90 deg mask+0.075: S1(-4.325,6.27) S2(4.325,6.27)
  oval 1.1x1.9 hole 0.6 slot 1.4 at 90 deg mask+0.075: S3(-4.325,2.09) S4(4.325,2.09)
  silkscreen extent -4.33,-0.5 4.33,7.69
BGA8_3-2-3_M040_1.24x1.75_WLCSP [mm] "BGA, 8 pin (170123)"
  round 0.21 smd mask+0.051: A1(-0.35,0.4) A3(0.35,0.4) B2(0,0.2) C1(-0.35,0) C3(0.35,0) D2(0,-0.2) E1(-0.35,-0.4) E3(0.35,-0.4)
  silkscreen extent -0.63,-0.89 0.63,0.88, body extent -0.63,-0.89 0.63,0.88, height 0.53
BGA120_M050_7.0X7.0_SL_EFM32GG12 [mm] "BGA, 120 Leads, Body 7.0x7.0mmx1,30mm, Pitch 0.50mm"
  round 0.2 smd mask+0.04: A1(-3,3) A2(-2.5,3) A3(-2,3) A4(-1.5,3) A5(-1,3) A6(-0.5,3) A7(0,3) A8(0.5,3) A9(1,3) A10(1.5,3) A11(2,3) A12(2.5,3) A13(3,3) B1(-3,2.5) B2(-2.5,2.5) B3(-2,2.5) B4(-1.5,2.5) B5(-1,2.5) B6(-0.5,2.5) B7(0,2.5) B8(0.5,2.5) B9(1,2.5) B10(1.5,2.5) B11(2,2.5) B12(2.5,2.5) B13(3,2.5) C1(-3,2) C2(-2.5,2) C3(-2,2) C4(-1.5,2) C5(-1,2) C6(-0.5,2) C7(0,2) C8(0.5,2) C9(1,2) C10(1.5,2) C11(2,2) C12(2.5,2) C13(3,2) D1(-3,1.5) D2(-2.5,1.5) D3(-2,1.5) D11(2,1.5) D12(2.5,1.5) D13(3,1.5) E1(-3,1) E2(-2.5,1) E3(-2,1) E11(2,1) E12(2.5,1) E13(3,1) F1(-3,0.5) F2(-2.5,0.5) F3(-2,0.5) F11(2,0.5) F12(2.5,0.5) F13(3,0.5) G1(-3,0) G2(-2.5,0) G3(-2,0) G11(2,0) G12(2.5,0) G13(3,0) H1(-3,-0.5) H2(-2.5,-0.5) H3(-2,-0.5) H11(2,-0.5) H12(2.5,-0.5) H13(3,-0.5) J1(-3,-1) J2(-2.5,-1) J3(-2,-1) J11(2,-1) J12(2.5,-1) J13(3,-1) K1(-3,-1.5) K2(-2.5,-1.5) K3(-2,-1.5) K11(2,-1.5) K12(2.5,-1.5) K13(3,-1.5) L1(-3,-2) L2(-2.5,-2) L3(-2,-2) L4(-1.5,-2) L5(-1,-2) L6(-0.5,-2) L7(0,-2) L8(0.5,-2) L9(1,-2) L10(1.5,-2) L11(2,-2) L12(2.5,-2) L13(3,-2) M1(-3,-2.5) M2(-2.5,-2.5) M3(-2,-2.5) M4(-1.5,-2.5) M5(-1,-2.5) M6(-0.5,-2.5) M7(0,-2.5) M8(0.5,-2.5) M9(1,-2.5) M10(1.5,-2.5) M11(2,-2.5) M12(2.5,-2.5) M13(3,-2.5) N1(-3,-3) N2(-2.5,-3) N3(-2,-3) N4(-1.5,-3) N5(-1,-3) N6(-0.5,-3) N7(0,-3) N8(0.5,-3) N9(1,-3) N10(1.5,-3) N11(2,-3) N12(2.5,-3) N13(3,-3)
  silkscreen extent -3.5,-3.5 3.5,3.5, body extent -3.5,-3.5 3.5,3.5, height 1.3
BOSCH_BMP384_LGA10_M050_2.0X2.0 [mm] "(210607)"
  rrect10% 0.27x0.285 smd paste-0.025 mask+0.05: 1(0.25,0.757) 2(-0.25,0.757) 6(-0.25,-0.757) 7(0.25,-0.757)
  rrect10% 0.285x0.27 smd paste-0.025 mask+0.05: 3(-0.757,0.5) 4(-0.757,0) 5(-0.757,-0.5) 8(0.757,-0.5) 9(0.757,0) 10(0.757,0.5)
  silkscreen extent -1,-1 1,1, body extent -1,-1 1,1, height 1.01
C0201_L [mm] "Capacitor"
  rrect25% 0.36x0.32 smd: 1(-0.275,0) 2(0.275,0)
  silkscreen extent -0.29,-0.15 0.29,0.15, body extent -0.32,-0.13 0.32,0.13, height 0.3
C0402_L [mm] "Chip Capacitor, 2-Leads, Body 1.0x0.5mm, IPC High Density (170201)"
  rrect20% 0.6x0.5 smd mask+0.051: 1(-0.45,0) 2(0.45,0)
  silkscreen extent -0.5,-0.25 0.5,0.25, body extent -0.5,-0.25 0.5,0.25, height 0.6
C0603_L [mm] "Capacitor, 0603, High Density (C) (170201)"
  rrect25% 0.8x0.85 smd: 1(-0.7,0) 2(0.7,0)
  silkscreen extent -0.88,-0.48 0.87,0.48, body extent -0.88,-0.48 0.87,0.48, height 0.95
C0805_L [mm] "Capacitor, 0805"
  rrect25% 0.95x1.35 smd: 1(-0.8,0) 2(0.8,0)
  silkscreen extent -1.12,-0.72 1.1,0.72, body extent -1.1,-0.72 1.1,0.72, height 1.45
COIL_0201_L [mm] "Inductor, 0201, High Density (C)"
  rrect10% 0.37x0.32 smd: 1(-0.27,0) 2(0.27,0)
  silkscreen extent -0.32,-0.17 0.32,0.17, body extent -0.32,-0.17 0.32,0.17, height 0.33
COIL_BOURNS_SDR0604 [mm] "Coil Bourns SDR0604 (210208)"
  rrect20% 1x1 smd paste-100: 1(-2,0) 2(2,0)
  Top Layer region: -3,-2.101 -3,2.1 -3,2.179 -2.969,2.333 -2.909,2.479 -2.822,2.61 -2.71,2.722 -2.579,2.809 -2.433,2.869 -2.279,2.9 -2.2,2.9 -2.2,2.9 -1,2.9 -0.98,2.9 -0.943,2.885 -0.915,2.857 -0.9,2.82 -0.9,2.8 -0.9,2.8 -0.9,-2.8 -0.9,-2.82 -0.915,-2.857 -0.943,-2.885 -0.98,-2.9 -1,-2.9 -1,-2.9 -2.2,-2.9 -2.279,-2.9 -2.433,-2.869 -2.578,-2.809 -2.709,-2.722 -2.821,-2.61 -2.909,-2.48 -2.969,-2.334 -3,-2.18 -3,-2.101
  Top Layer region: 3,2.101 3,-2.1 3,-2.179 2.969,-2.333 2.909,-2.479 2.822,-2.61 2.71,-2.722 2.579,-2.809 2.433,-2.869 2.279,-2.9 2.2,-2.9 2.2,-2.9 1,-2.9 0.98,-2.9 0.943,-2.885 0.915,-2.857 0.9,-2.82 0.9,-2.8 0.9,-2.8 0.9,2.8 0.9,2.82 0.915,2.857 0.943,2.885 0.98,2.9 1,2.9 1,2.9 2.2,2.9 2.279,2.9 2.433,2.869 2.578,2.809 2.709,2.722 2.821,2.61 2.909,2.48 2.969,2.334 3,2.18 3,2.101
  silkscreen extent -2.9,-2.91 2.9,2.91, body extent -2.9,-2.9 2.9,2.9, height 4.81
DFN6_3X3MM_SI7021 [mm]
  rrect20% 0.85x0.45 smd: 1(-1.45,1) 2(-1.45,0) 3(-1.45,-1) 4(1.45,-1) 5(1.45,0) 6(1.45,1)
  rrect20% 1.6x2.5 smd: 7(0,0)
  silkscreen extent -1.5,-1.5 1.5,1.5, body extent -1.5,-1.5 1.5,1.5, height 1.22
DO220AA [mm] "Diode DO220AA (DO-220AA) (= SMP) (Vishay) (170512)"
  rrect20% 2.67x2.3 smd: 1(-0.85,0)
  rrect20% 1x1.27 smd: 2(1.8,0)
  silkscreen extent -2,-1.09 2.1,1.09, body extent -2,-1.09 2.1,1.09, height 1.15
FTSH_105_01_L_DV_K [mm]
  rrect20% 0.74x2.55 smd mask+0.051: 1(-2.54,-2.035) 2(-2.54,2.035) 3(-1.27,-2.035) 4(-1.27,2.035) 5(0,-2.035) 6(0,2.035) 7(1.27,-2.035) 8(1.27,2.035) 9(2.54,-2.035) 10(2.54,2.035)
  silkscreen extent -3.17,-1.72 3.17,1.72, body extent -3.23,-1.76 3.22,1.77, height 5.56
HDR_M254-1X10_PLUS_1X10_NO_3D [mm] "No 3D model for this component"
  round 1.6 hole 1: 1(0,-32.961) 2(0,0) 3(2.54,-32.961) 4(2.54,0) 5(5.08,-32.961) 6(5.08,0) 7(7.62,-32.961) 8(7.62,0) 9(10.16,-32.961) 10(10.16,0) 11(12.7,-32.961) 12(12.7,0) 13(15.24,-32.961) 14(15.24,0) 15(17.78,-32.961) 16(17.78,0) 17(20.32,-32.961) 18(20.32,0) 19(22.86,-32.961) 20(22.86,0)
  silkscreen extent -1.4,-34.23 24.13,1.27
HOLE_2.2_NPL [mm]
  round 0 hole 2.2 unplated mask+0.1: 1(0,0)
HRS_DF13C-2P-1.25V [mm]
  rrect20% 0.7x1.8 smd: 1(-0.625,-1.4) 2(0.625,-1.4)
  rrect20% 1.6x2.2 smd: 3(2.975,1.4) 4(-2.975,1.4)
  Mechanical 13 keep-out region: -0.975,1.97 0.975,1.97 0.975,-0.4 -0.975,-0.4
  silkscreen extent -3.57,-1.82 3.57,3.2, body extent -3.66,-1.85 3.65,3.23, height 4.8
LED_0402_CAT2 [mm] "(200921)"
  rrect10% 0.45x0.6 smd: 1(-0.45,0) 2(0.45,0)
  silkscreen extent -0.55,-0.33 0.55,0.33, body extent -0.55,-0.33 0.55,0.33, height 0.25
LED_LUMEX_SML-LX0404-4 [mm] "LED, LUMEX, SML LX0404 1.0x1.0x0.25 NB! Pin numbering"
  rrect25% 0.45x0.45 smd mask+0.05: 1(-0.425,-0.425) 2(-0.425,0.425) 3(0.425,0.425) 4(0.425,-0.425)
  silkscreen extent -0.5,-0.5 0.5,0.5, body extent -0.5,-0.5 0.5,0.5, height 0.31
LLP8_MA65_W3.0 [mm]
  rrect20% 0.5x0.25 smd: 1(-1.15,0.75) 2(-1.15,0.25) 3(-1.15,-0.25) 4(-1.15,-0.75) 5(1.15,-0.75) 6(1.15,-0.25) 7(1.15,0.25) 8(1.15,0.75)
  rrect20% 1.2x1.5 smd: 9(0,0)
  silkscreen extent -1.55,-1.3 1.55,1.3, body extent -1.55,-1.3 1.55,1.3, height 0.8
LOGO_ACCEL_SM [mm] "(210603)"
LOGO_GECKO_H4.0_SM [mm] "Silicon Labs, Gecko logo"
LOGO_HUMID_3.2X3.2_SM [mm] "(210603)"
LOGO_LC_SENSOR_SYMBOL [mm]
LOGO_LIGHT_SM [mm] "(210603)"
LOGO_MAGNET_SM [mm] "(210603)"
LOGO_PRESSURE [mm] "(210607)"
LOGO_QWIIC_GM21_W7.0 [mm] "Logo QWIIC GTO width 7.0 (200625)"
  silkscreen extent 0,0 7.11,2.22
LOGO_SEGGER_8.0X4.0_SM [mil] "(210607)"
